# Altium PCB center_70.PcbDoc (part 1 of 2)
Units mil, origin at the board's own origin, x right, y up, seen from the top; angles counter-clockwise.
Board outline 2598.41 x 2598.41 mil, 6 copper layers (Top Layer 1, GND, POWER, SIG, GND (Mid4), Bottom Layer 1), stack 67.411 mil thick; 185 components, 89 nets, 515 pads, 179 vias.
Unrouted connection lines stored in the file: 158.
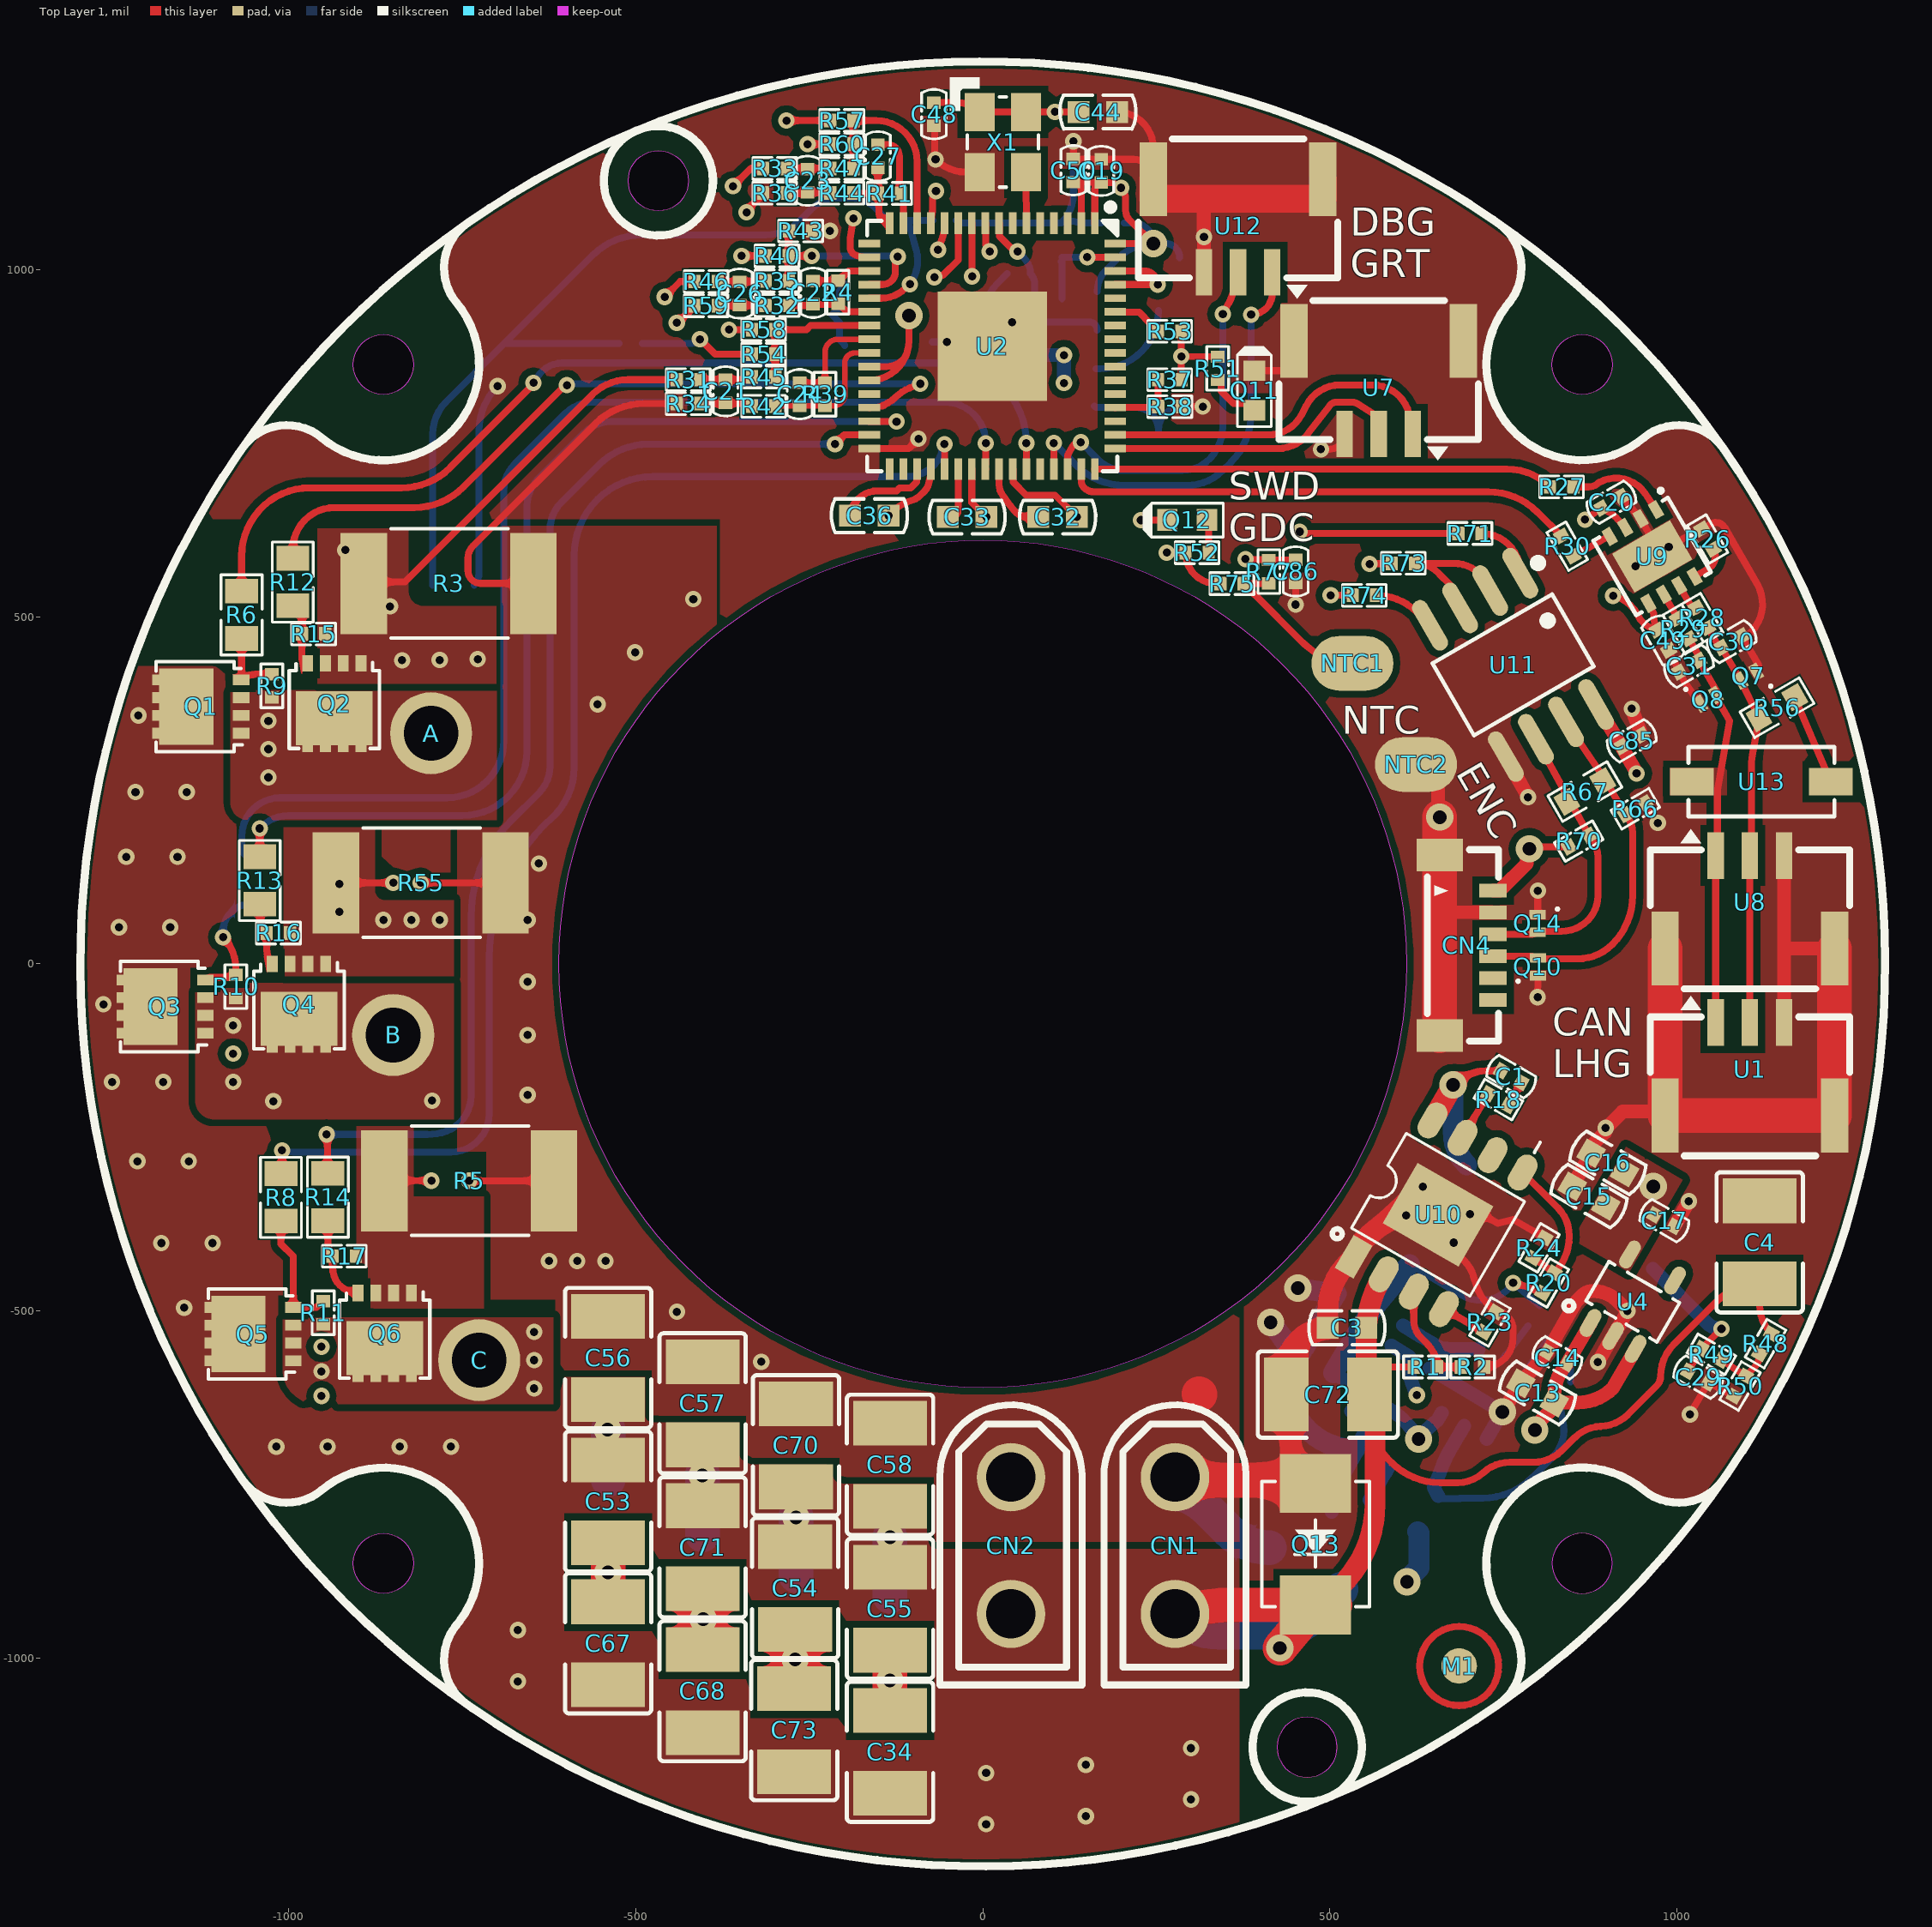
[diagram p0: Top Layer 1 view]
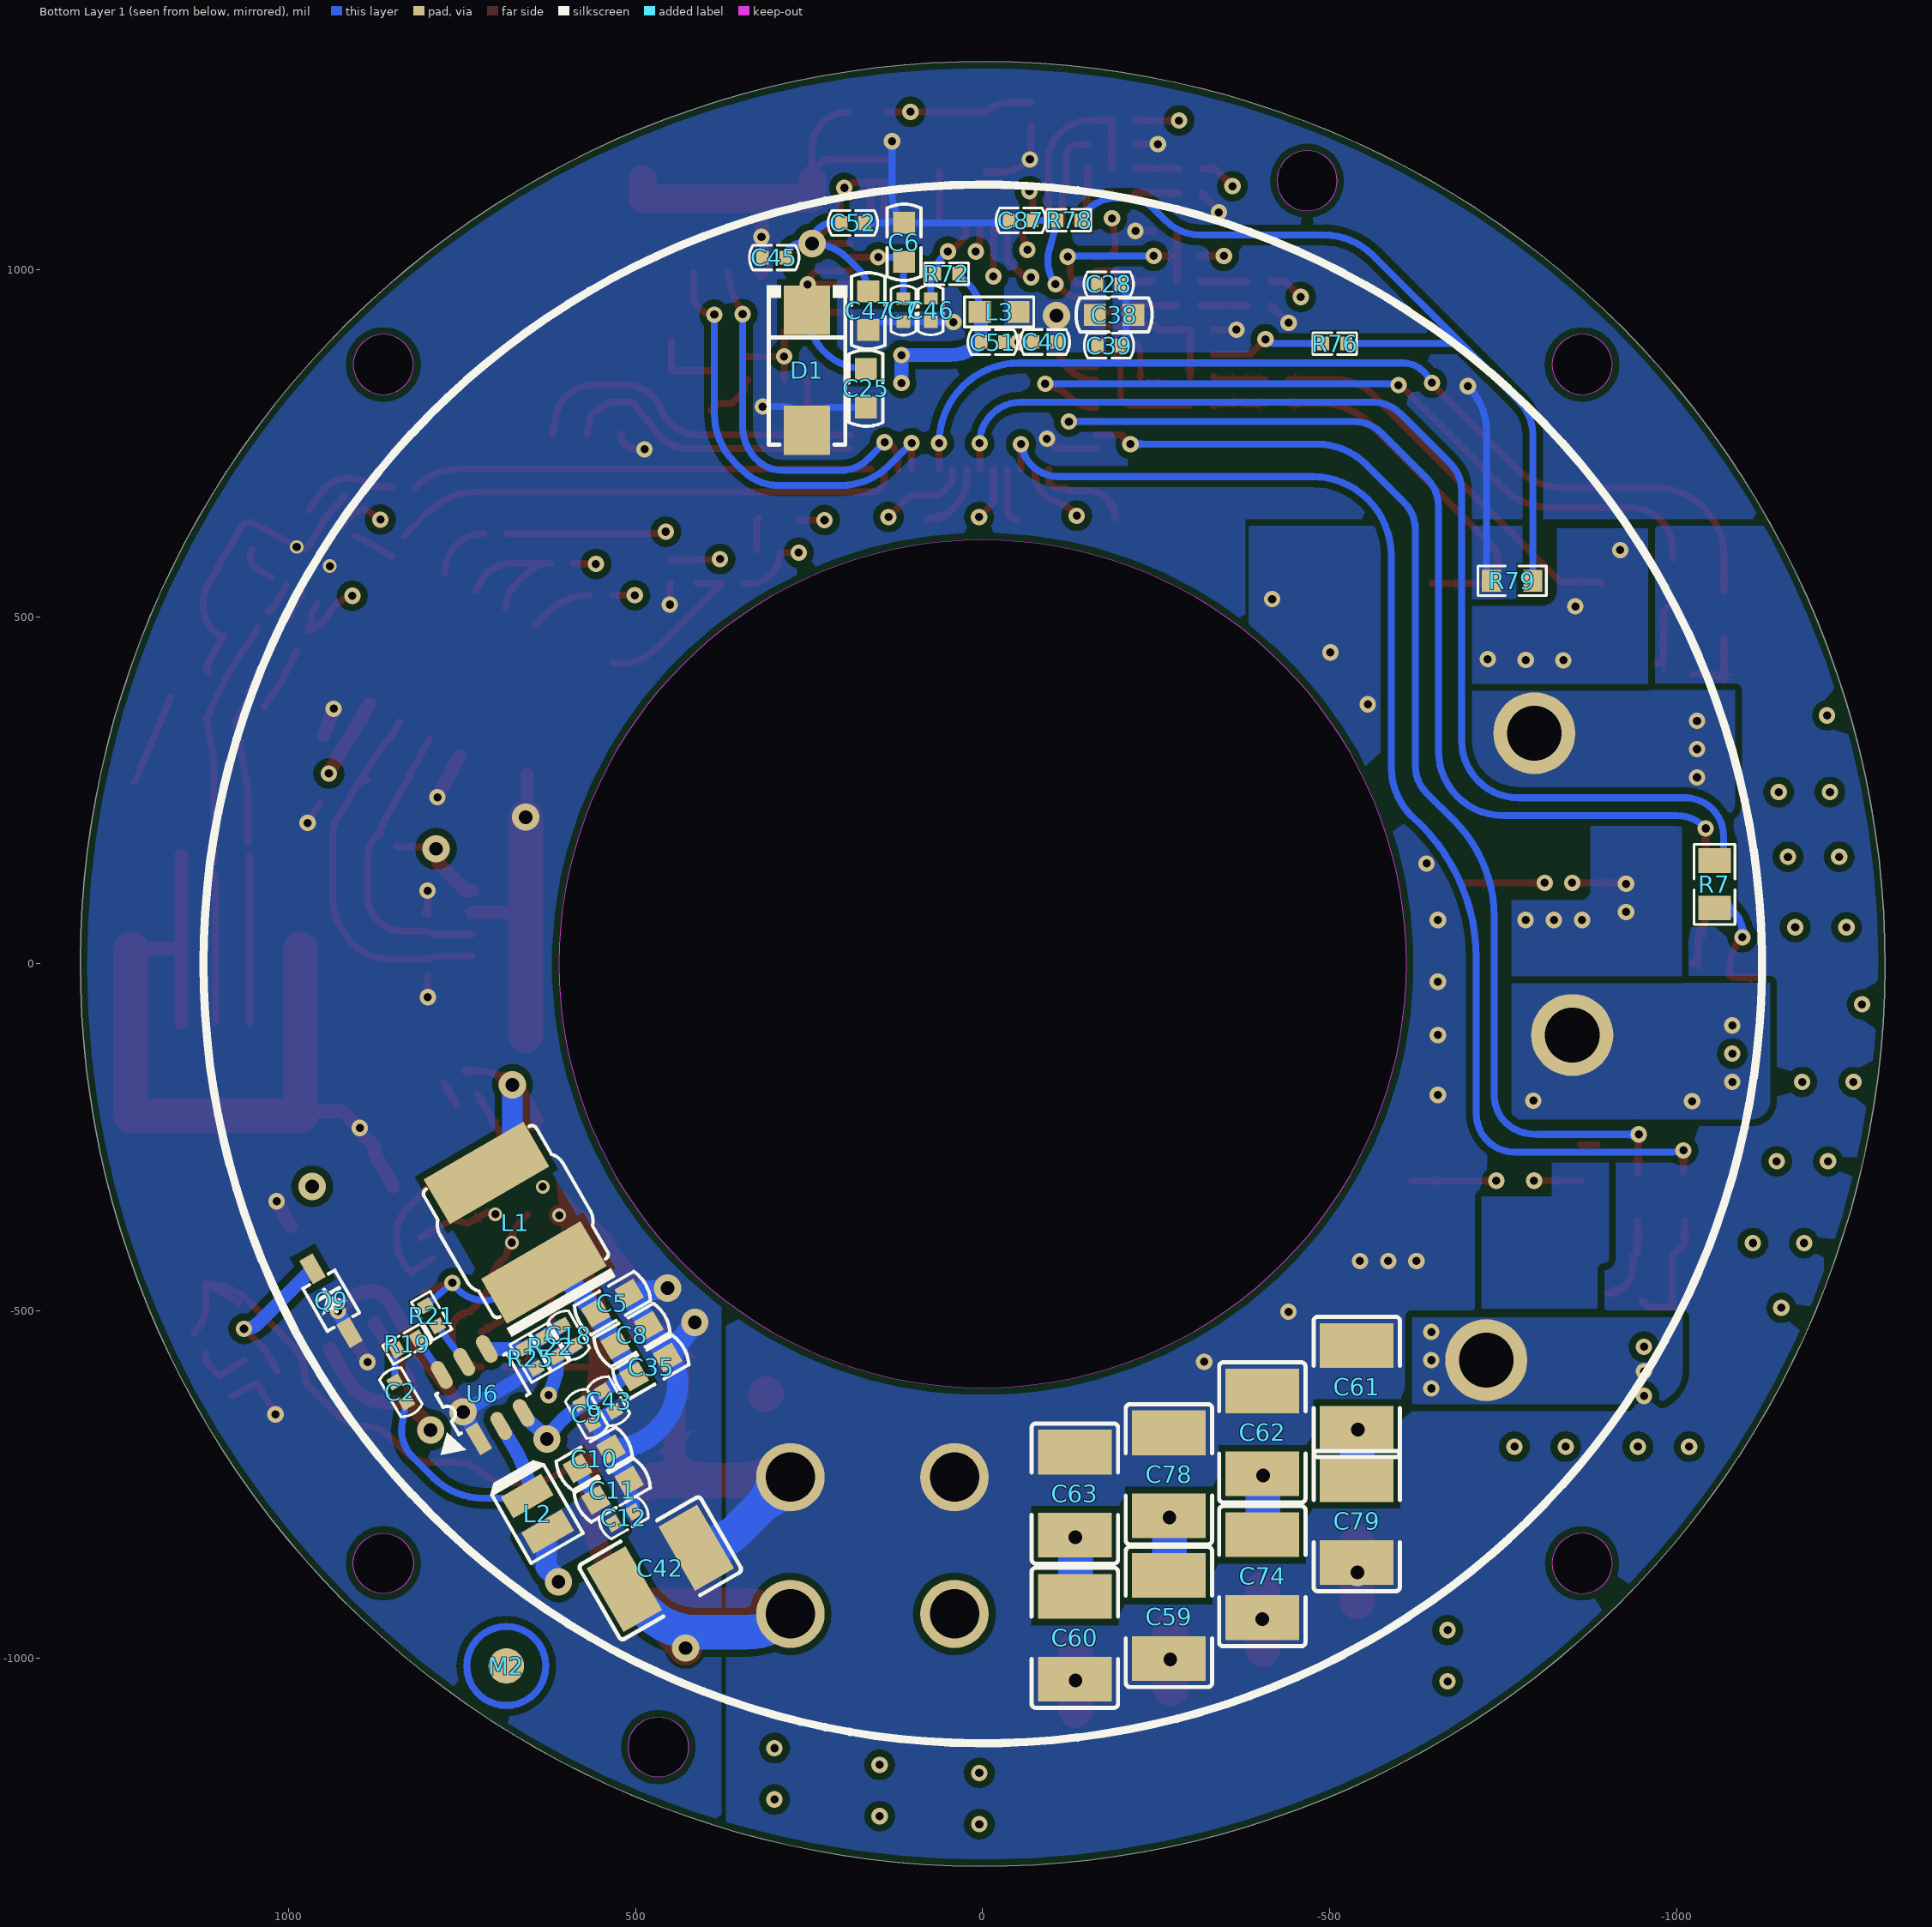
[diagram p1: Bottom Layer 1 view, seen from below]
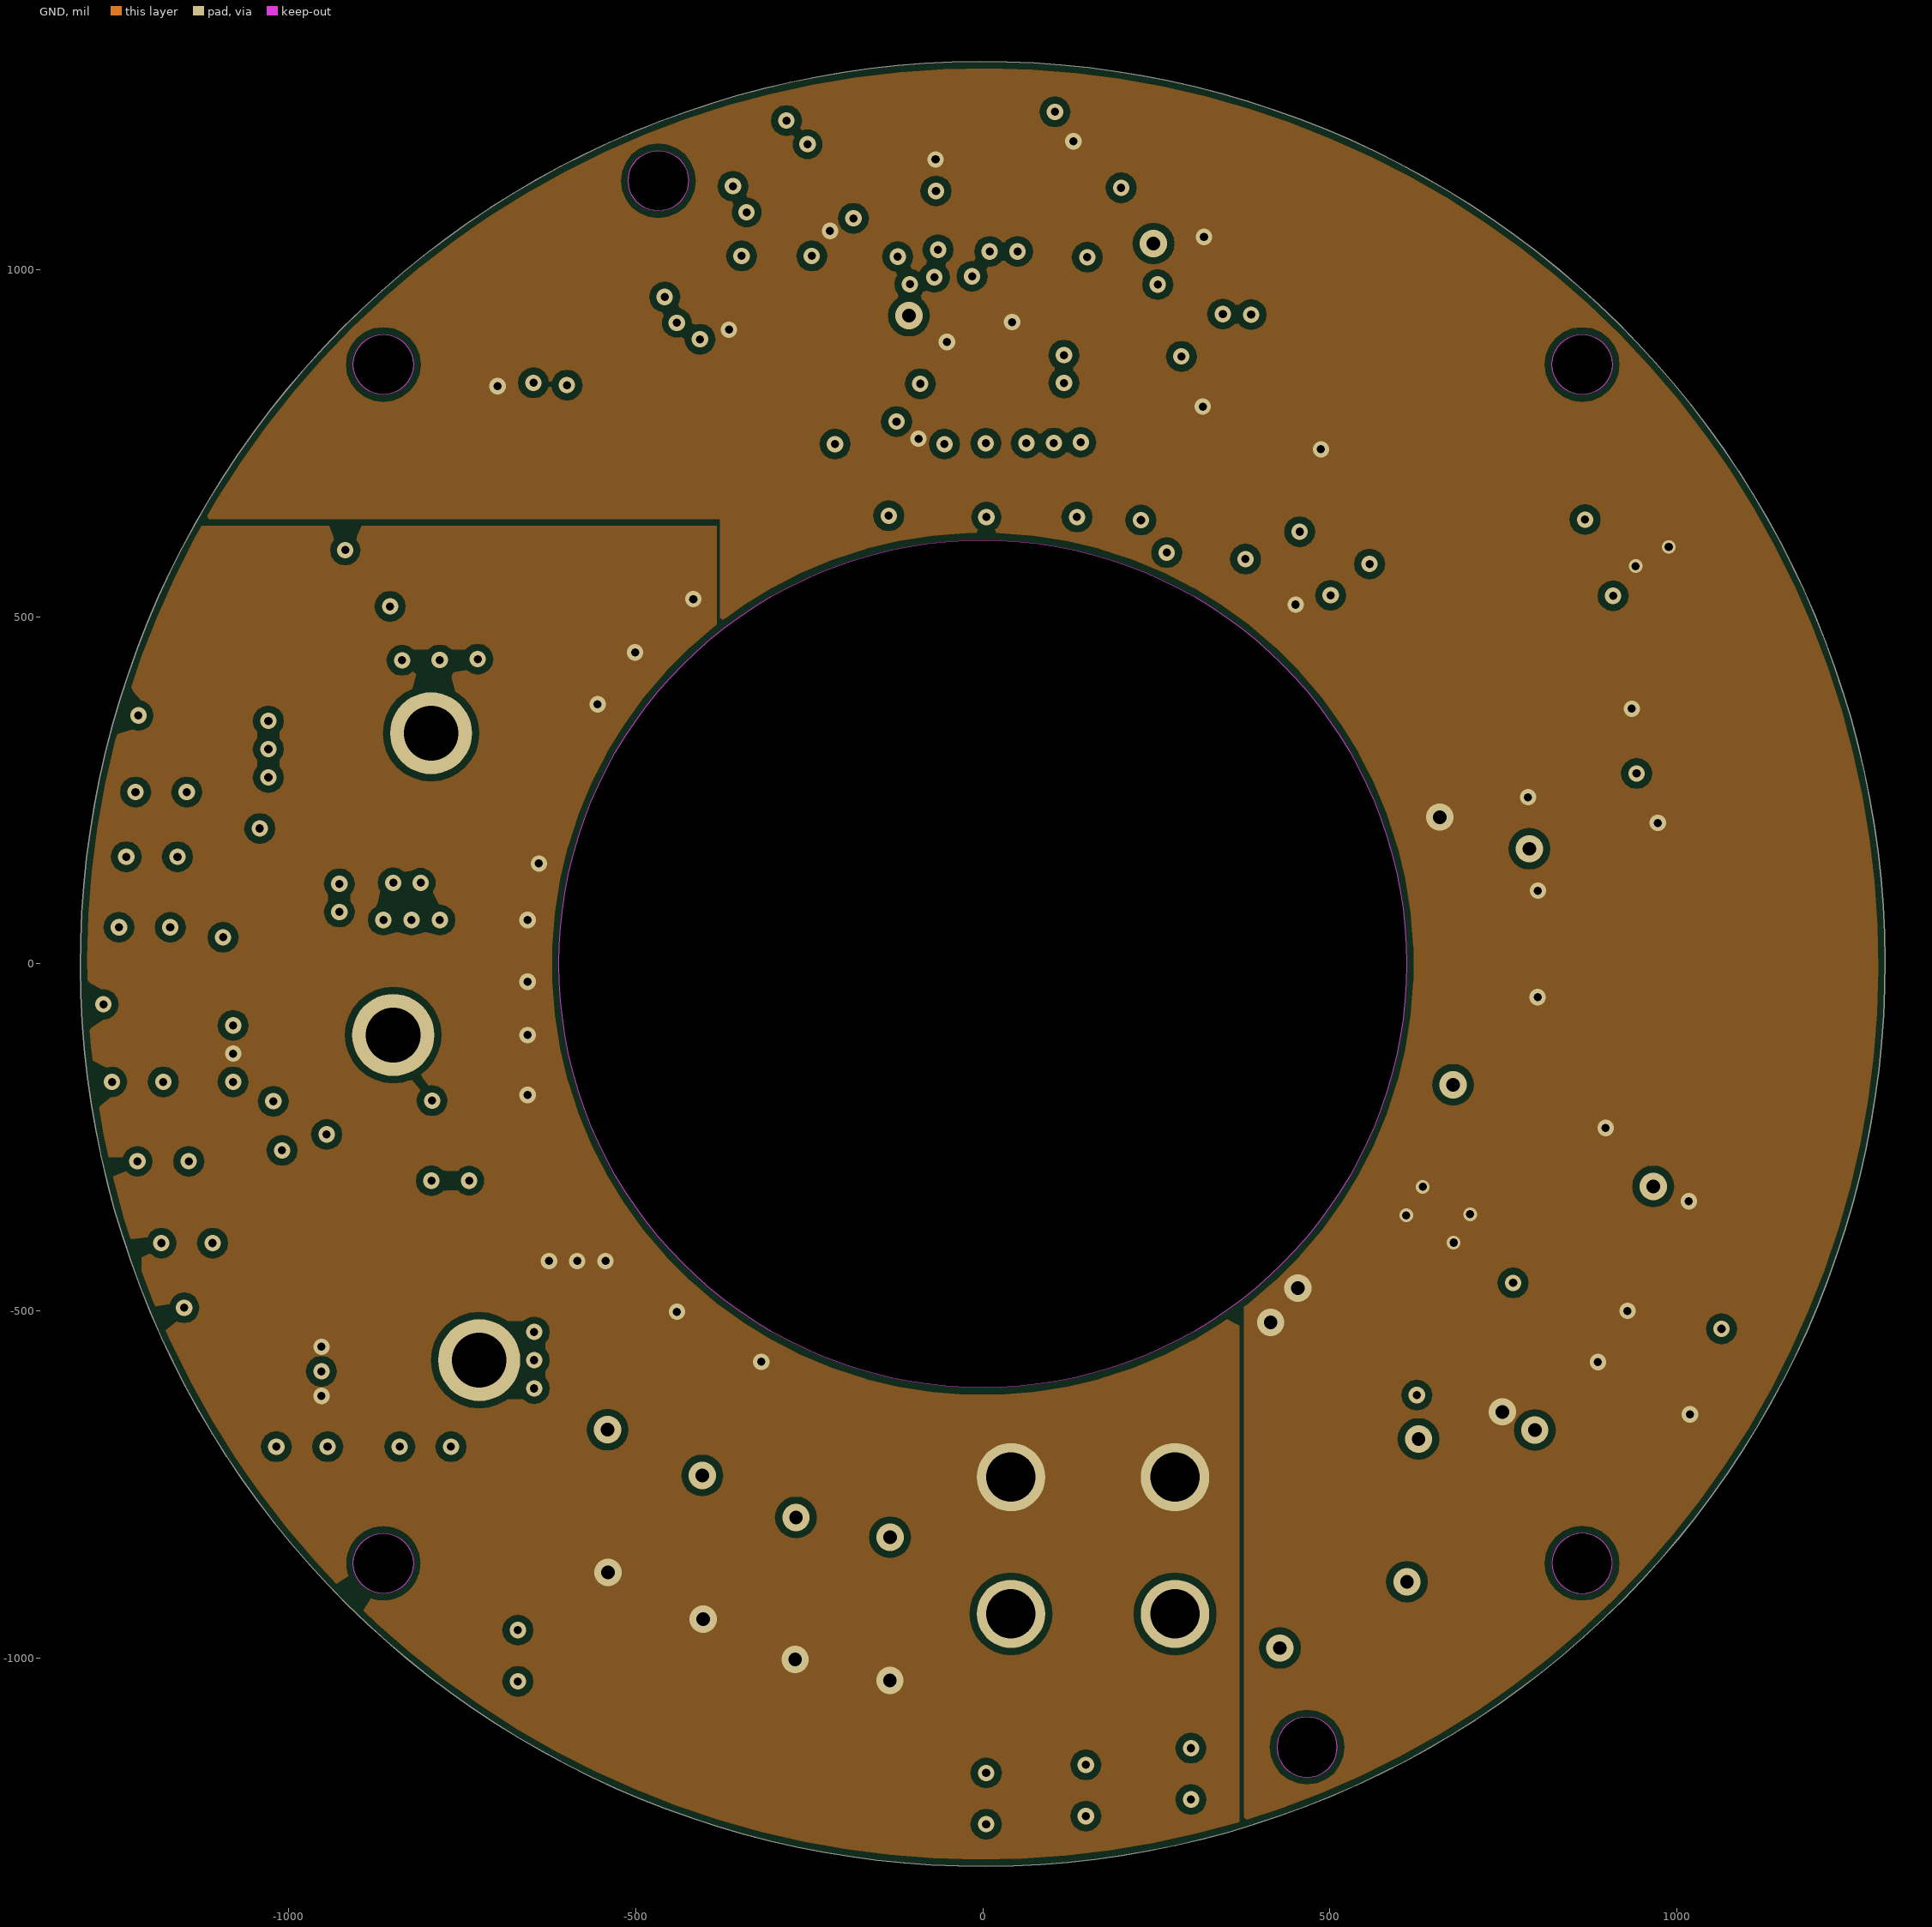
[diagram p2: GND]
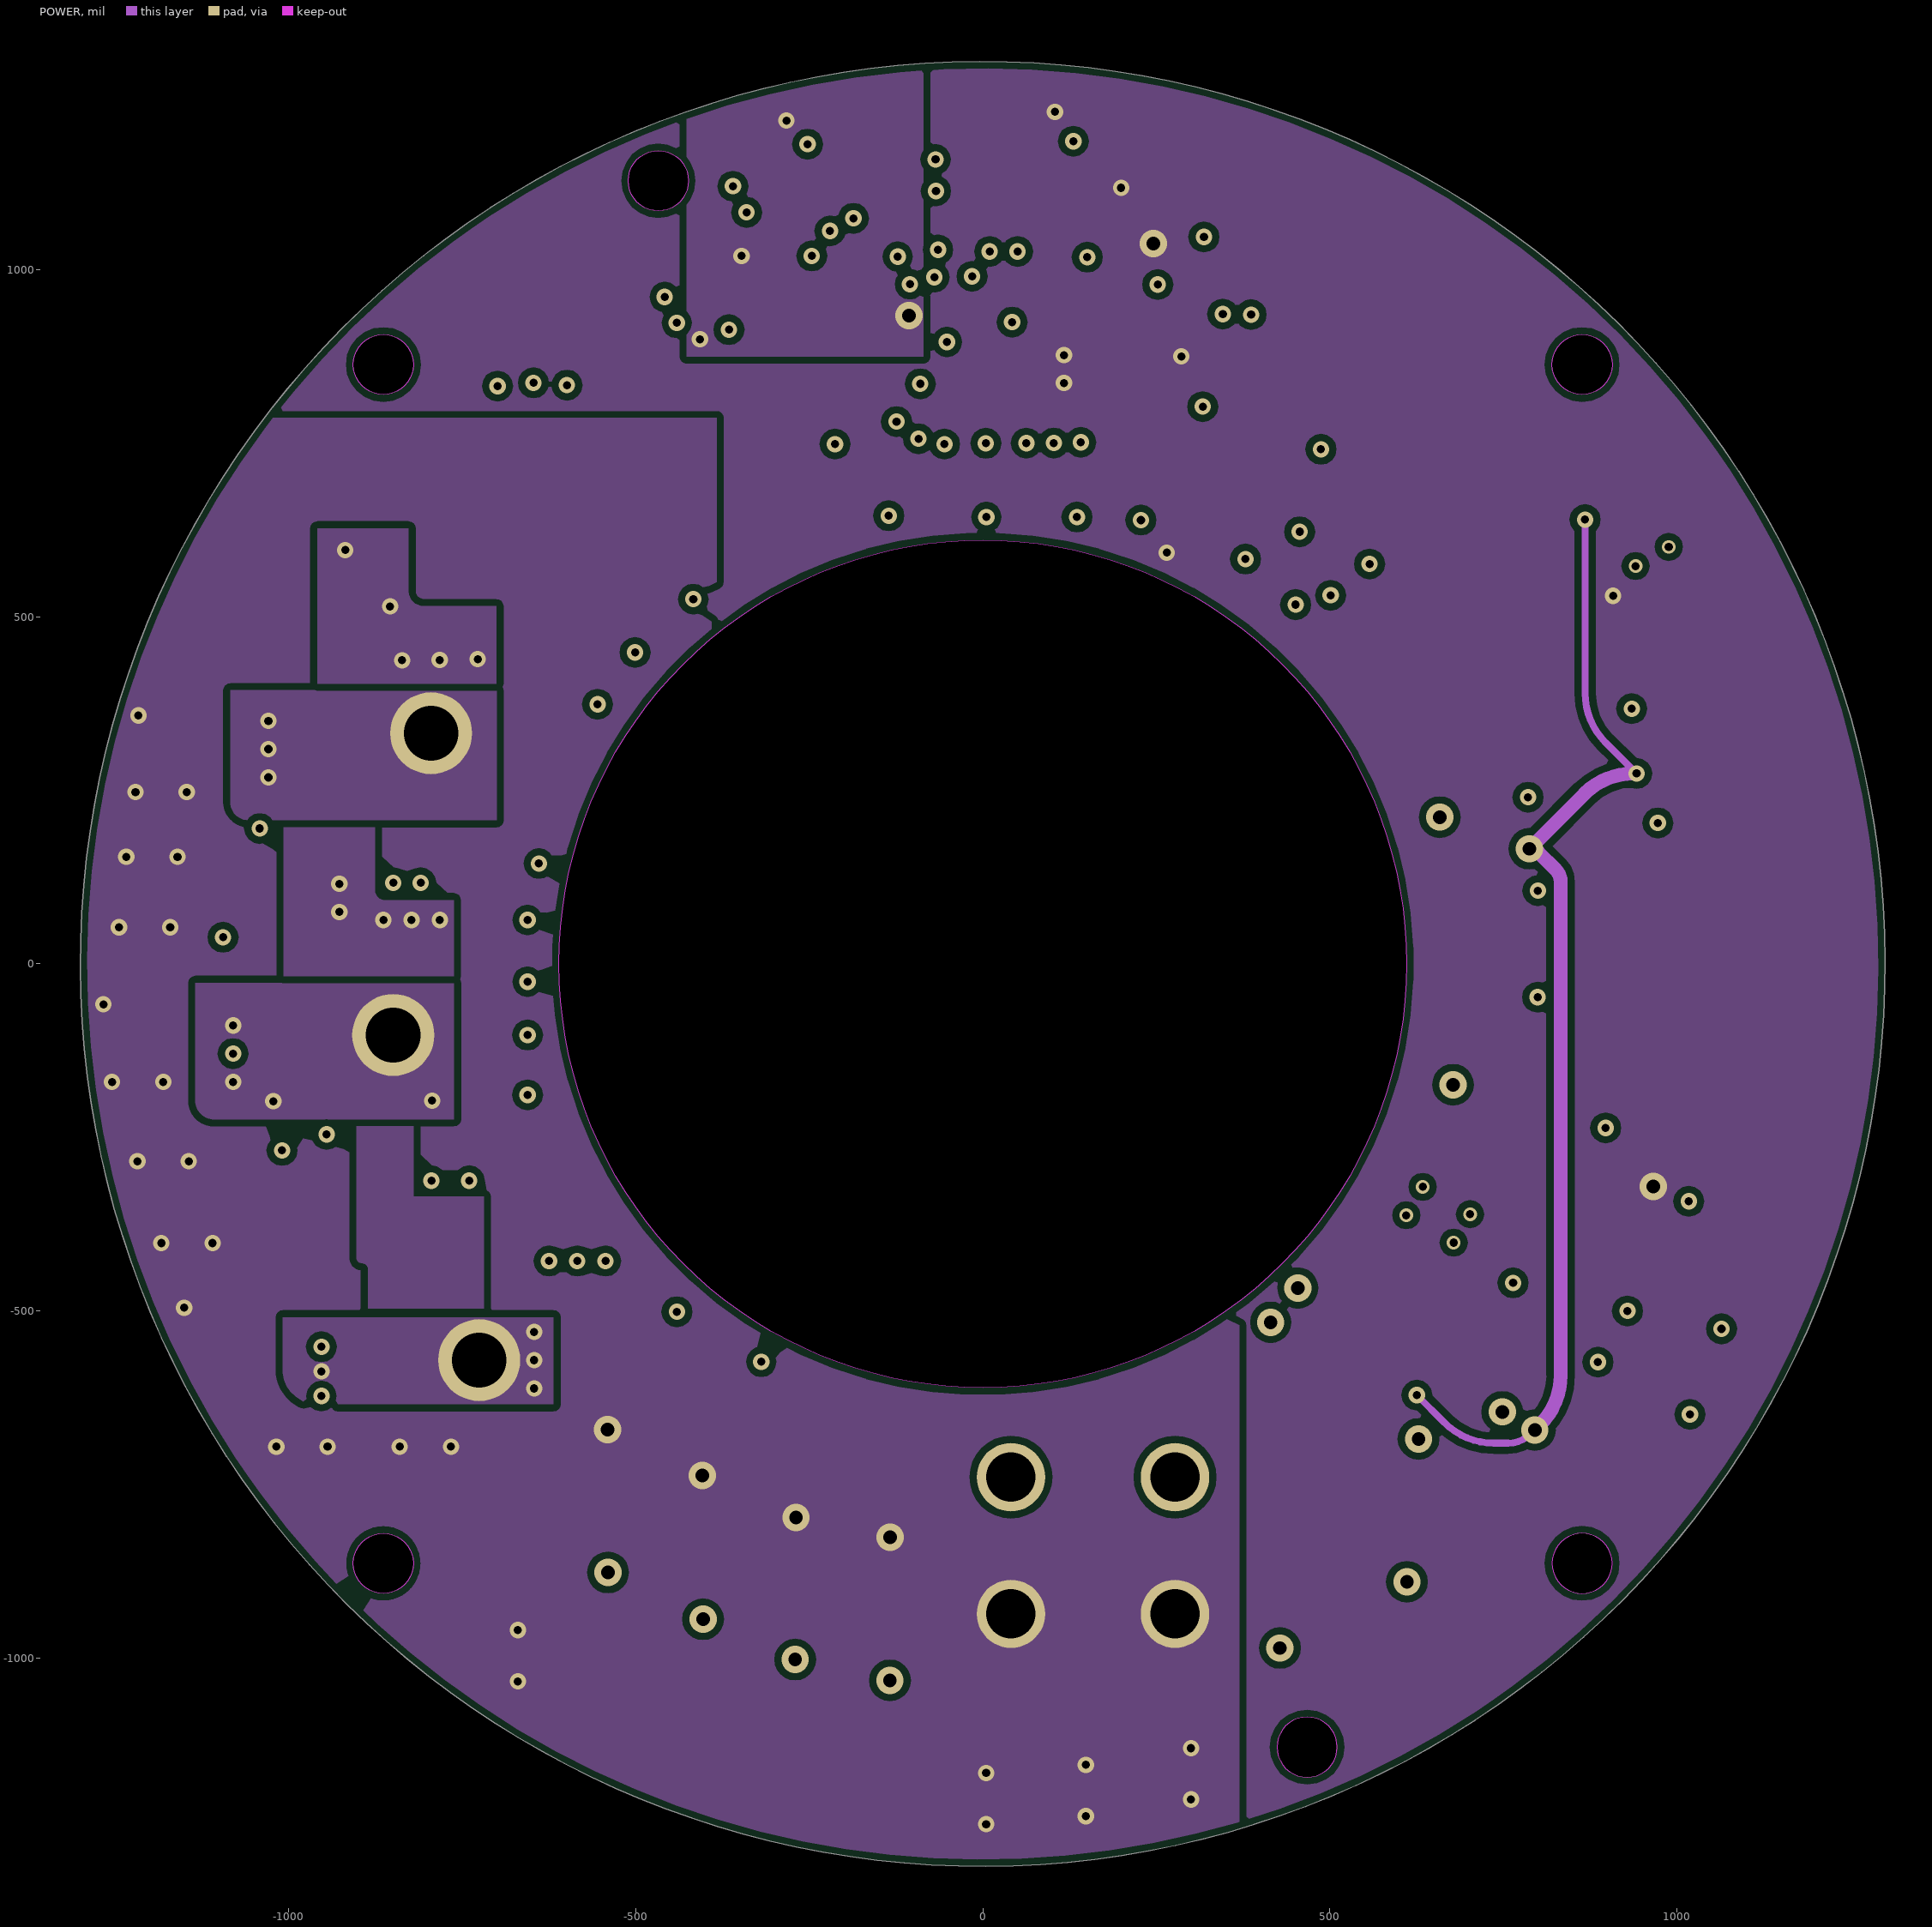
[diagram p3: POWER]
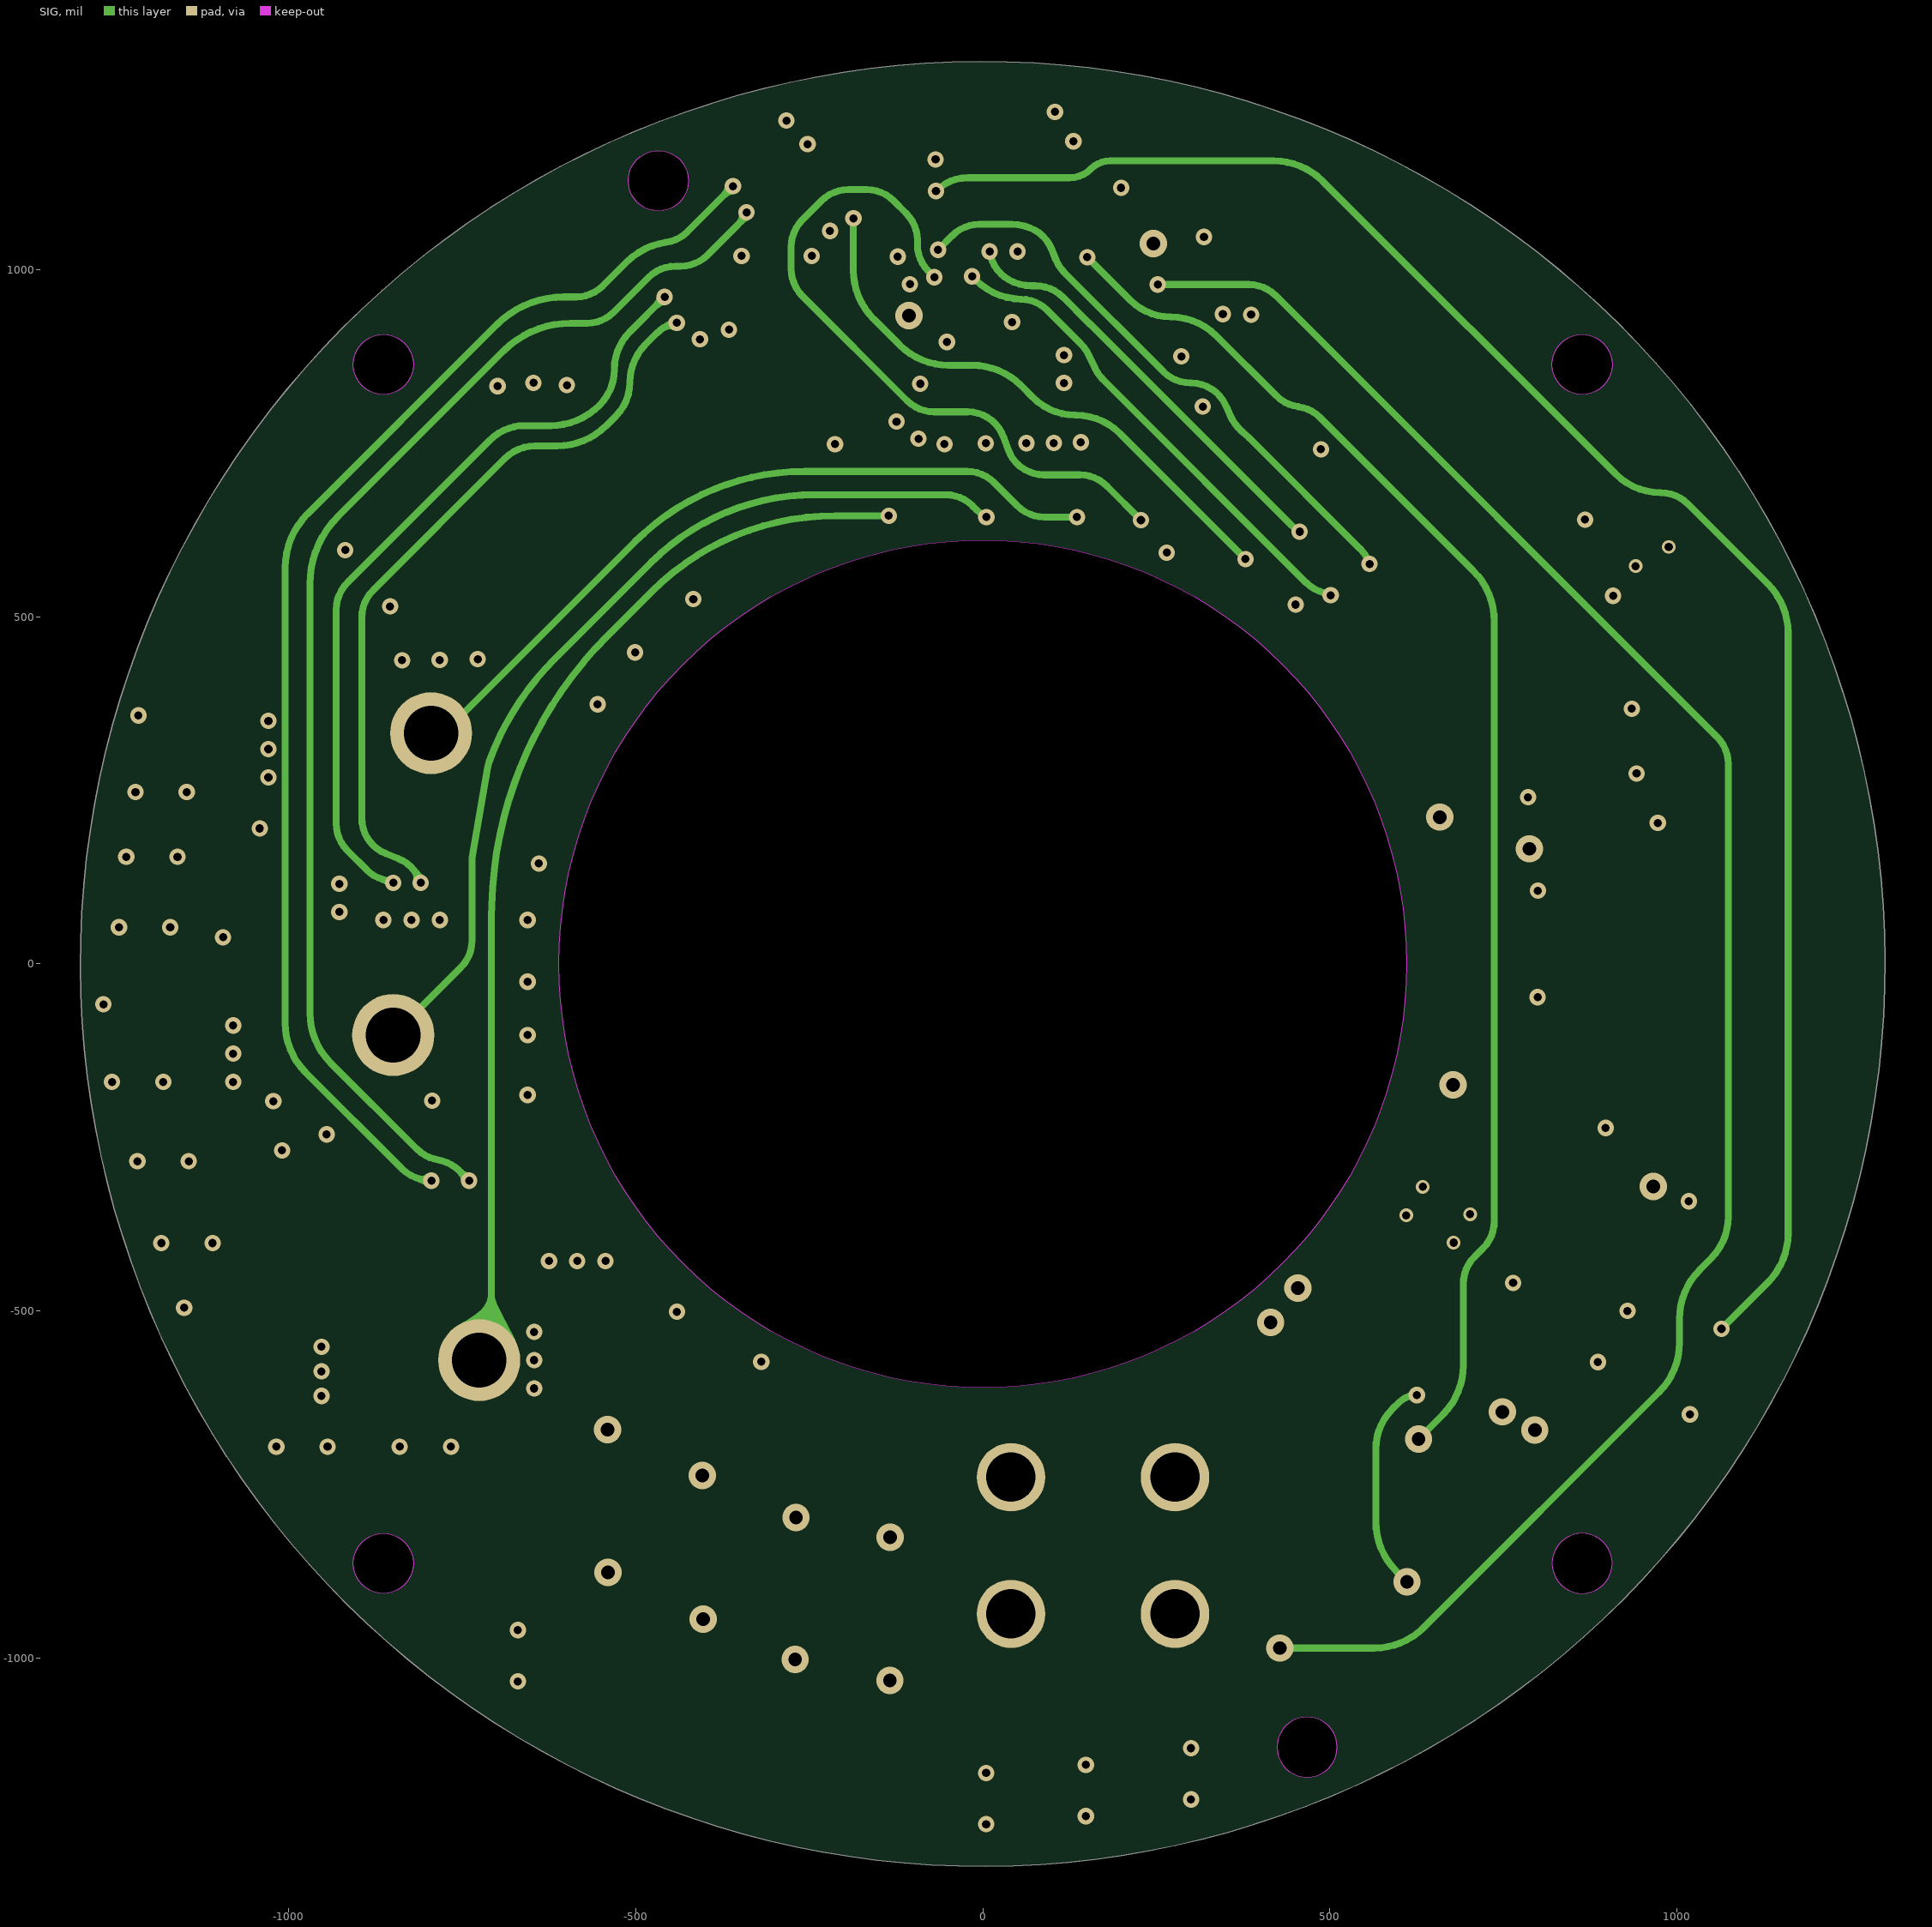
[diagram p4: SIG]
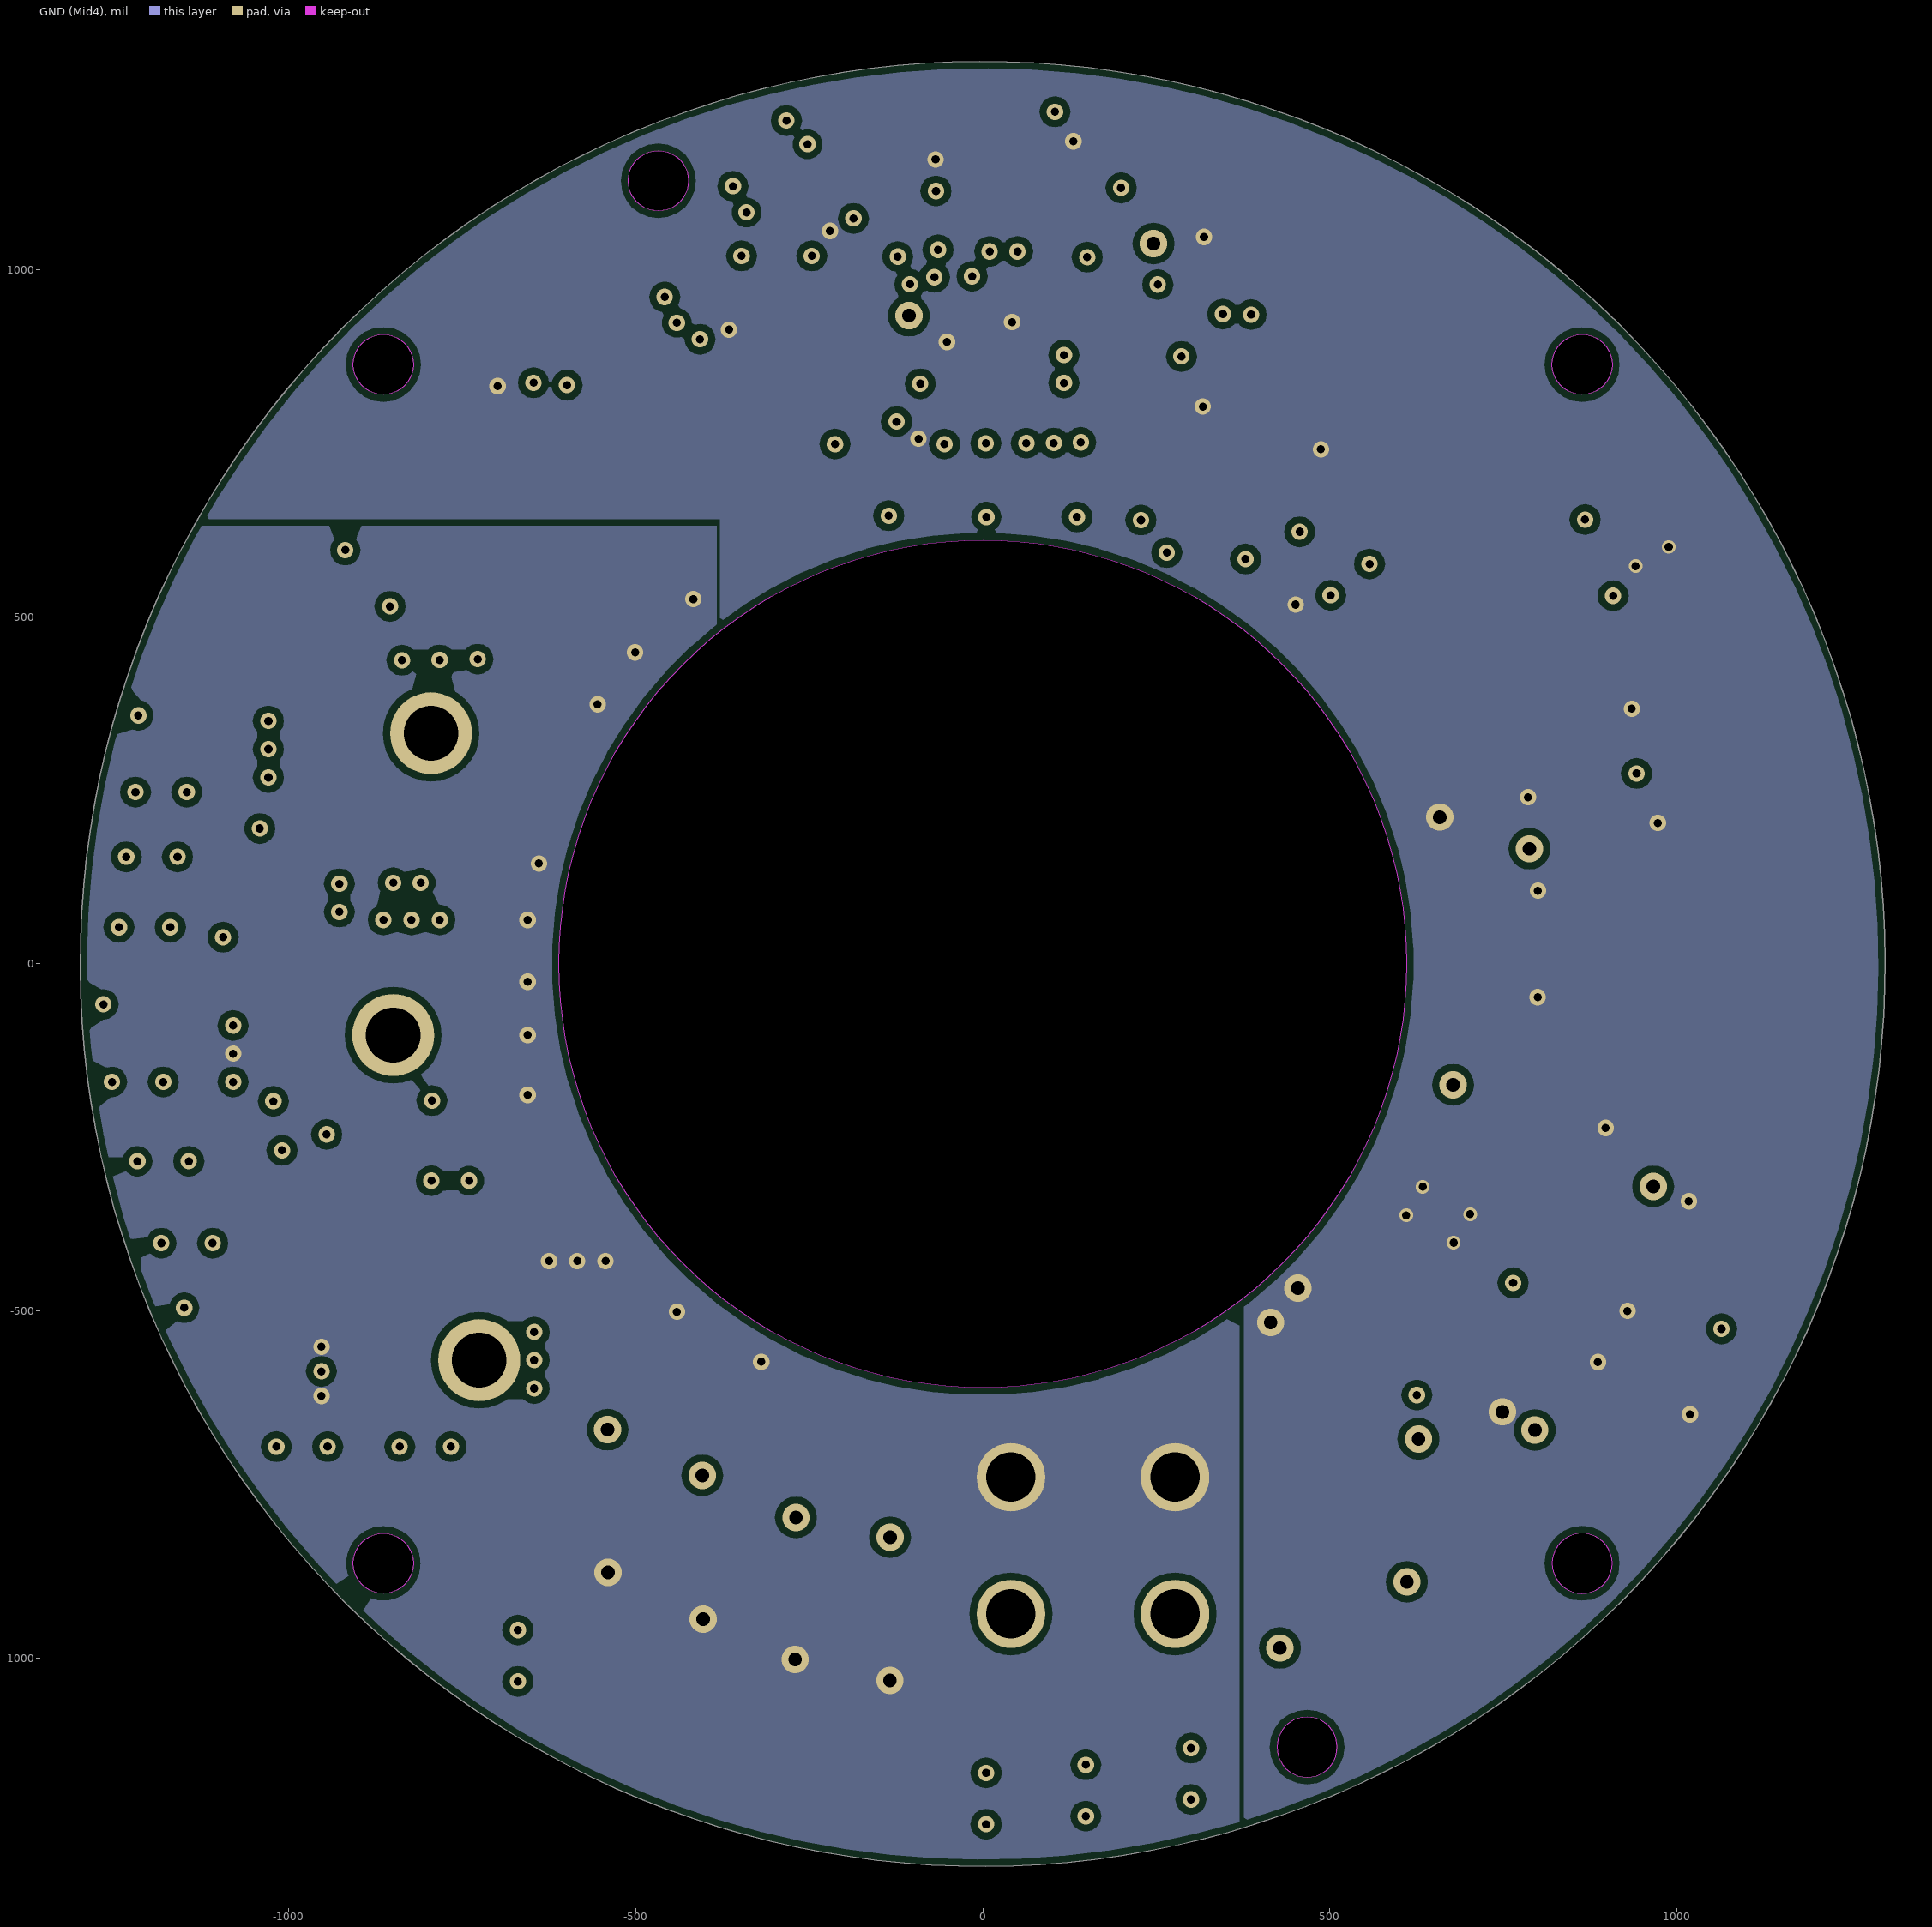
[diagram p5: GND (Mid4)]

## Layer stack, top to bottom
Top Solder: solder mask 1.9685, Solder Resist, Dk 3.5
Top Layer 1: signal copper 1.9685
Dielectric 2: prepreg 15.748, PP-006, Dk 4.1
GND: signal copper 1.378
Dielectric 4: prepreg 2.8, PP-006, Dk 4.1
POWER: signal copper 1.9685
Dielectric 1: dielectric 19.685, FR-4, Dk 4.8
SIG: signal copper 1.9685
Dielectric 5: prepreg 2.8, PP-006, Dk 4.1
GND (Mid4): signal copper 1.378
Dielectric 3: prepreg 15.748, PP-006, Dk 4.1
Bottom Layer 1: signal copper 1.9685
Bottom Solder: solder mask 1.9685, Solder Resist, Dk 3.5

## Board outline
-1066.59,-741.89 ccw(c-0.01,-0.01) 741.86,-1066.59 ccw(c-0.01,-0.01) 1066.56,741.86 ccw(c-0.01,-0.01) -741.89,1066.56 ccw(c-0.01,-0.01)
cut-out: 423.73,-1127.58 ccw(c467.04,-1127.58) 467.04,-1170.89 ccw(c467.04,-1127.58) 510.35,-1127.58 ccw(c467.04,-1127.58) 467.04,-1084.28 ccw(c467.04,-1127.58)
cut-out: 819.68,-863.02 ccw(c862.99,-863.02) 862.99,-906.33 ccw(c862.99,-863.02) 906.3,-863.02 ccw(c862.99,-863.02) 862.99,-819.71 ccw(c862.99,-863.02)
cut-out: 862.99,819.68 cw(c862.99,862.99) 819.68,862.99 cw(c862.99,862.99) 862.99,906.3 cw(c862.99,862.99) 906.3,862.99 cw(c862.99,862.99)
cut-out: -467.07,1084.25 cw(c-467.07,1127.56) -510.38,1127.56 cw(c-467.07,1127.56) -467.07,1170.86 cw(c-467.07,1127.56) -423.76,1127.56 cw(c-467.07,1127.56)
cut-out: -863.02,819.68 cw(c-863.02,862.99) -906.33,862.99 cw(c-863.02,862.99) -863.02,906.3 cw(c-863.02,862.99) -819.71,862.99 cw(c-863.02,862.99)
cut-out: -863.02,-906.33 cw(c-863.02,-863.02) -906.33,-863.02 cw(c-863.02,-863.02) -863.02,-819.71 cw(c-863.02,-863.02) -819.71,-863.02 cw(c-863.02,-863.02)
cut-out: 0,-610.24 cw(c0,0) -610.24,0 cw(c0,0) 0,610.24 cw(c0,0) 610.24,0 cw(c0,0)

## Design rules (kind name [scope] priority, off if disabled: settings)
BoardOutlineClearance [All] p1: gap=10 ignorepadtopadclearanceinfootprint=FALSE except(0: Arc-SplitContinuation Track-SplitContinuation SMDPad-SplitContinuation THPad-SplitContinuation Via-SplitContinuation Fill-SplitContinuation Poly-SplitContinuation Region-SplitContinuation Text-SplitContinuation)
Clearance [All] p1: gap=10 ignorepadtopadclearanceinfootprint=FALSE except(0: Arc-Hole Track-Hole SMDPad-Hole THPad-Hole Via-Hole Fill-Hole Poly-Hole Region-Hole Text-Hole; 7: Arc-Arc Arc-Track Arc-SMDPad Arc-THPad Arc-Via Track-Track Track-SMDPad Track-THPad Track-Via SMDPad-SMDPad SMDPad-THPad SMDPad-Via THPad-THPad THPad-Via Via-Via)
PlaneConnect [All] p1: planeconnectstyle=Direct reliefexpansion=20 reliefentries=4 reliefconductorwidth=10 reliefairgap=10
PolygonConnect PolygonConnect_25 [All vs IsNamedPolygon('GND-GND')] p1: connectstyle=Direct reliefconductorwidth=10 reliefentries=4 polygonreliefangle="90 Angle" airgapwidth=10
PolygonConnect PolygonConnect_24 [All vs IsNamedPolygon('GND-GND 1')] p2: connectstyle=Direct reliefconductorwidth=10 reliefentries=4 polygonreliefangle="90 Angle" airgapwidth=10
PolygonConnect PolygonConnect_23 [All vs IsNamedPolygon('POWER-3V3')] p3: connectstyle=Direct reliefconductorwidth=10 reliefentries=4 polygonreliefangle="90 Angle" airgapwidth=10
PolygonConnect PolygonConnect_22 [All vs IsNamedPolygon('Top Layer 1-GND')] p4: connectstyle=Direct reliefconductorwidth=10 reliefentries=4 polygonreliefangle="90 Angle" airgapwidth=10
PolygonConnect PolygonConnect_21 [All vs IsNamedPolygon('Top Layer 1-48V')] p5: connectstyle=Direct reliefconductorwidth=10 reliefentries=4 polygonreliefangle="90 Angle" airgapwidth=10
PolygonConnect PolygonConnect_20 [All vs IsNamedPolygon('Top Layer 1-C')] p6: connectstyle=Direct reliefconductorwidth=10 reliefentries=4 polygonreliefangle="90 Angle" airgapwidth=10
PolygonConnect PolygonConnect_19 [All vs IsNamedPolygon('Top Layer 1-NetQ6_S')] p7: connectstyle=Direct reliefconductorwidth=10 reliefentries=4 polygonreliefangle="90 Angle" airgapwidth=10
PolygonConnect PolygonConnect_18 [All vs IsNamedPolygon('Top Layer 1-B')] p8: connectstyle=Direct reliefconductorwidth=10 reliefentries=4 polygonreliefangle="90 Angle" airgapwidth=10
PolygonConnect PolygonConnect_17 [All vs IsNamedPolygon('Top Layer 1-NetQ4_S')] p9: connectstyle=Direct reliefconductorwidth=10 reliefentries=4 polygonreliefangle="90 Angle" airgapwidth=10
PolygonConnect PolygonConnect_16 [All vs IsNamedPolygon('Top Layer 1-A')] p10: connectstyle=Direct reliefconductorwidth=10 reliefentries=4 polygonreliefangle="90 Angle" airgapwidth=10
PolygonConnect PolygonConnect_15 [All vs IsNamedPolygon('Top Layer 1-NetQ2_S')] p11: connectstyle=Direct reliefconductorwidth=10 reliefentries=4 polygonreliefangle="90 Angle" airgapwidth=10
PolygonConnect PolygonConnect_14 [All vs IsNamedPolygon('POWER-3V3')] p12: connectstyle=Direct reliefconductorwidth=10 reliefentries=4 polygonreliefangle="90 Angle" airgapwidth=10
PolygonConnect PolygonConnect_13 [All vs IsNamedPolygon('POWER-A3V3')] p13: connectstyle=Direct reliefconductorwidth=10 reliefentries=4 polygonreliefangle="90 Angle" airgapwidth=10
PolygonConnect PolygonConnect_12 [All vs IsNamedPolygon('Top Layer 1-5V')] p14: connectstyle=Direct reliefconductorwidth=10 reliefentries=4 polygonreliefangle="90 Angle" airgapwidth=10
PolygonConnect PolygonConnect_11 [All vs IsNamedPolygon('Top Layer 1-GND 2')] p15: connectstyle=Direct reliefconductorwidth=10 reliefentries=4 polygonreliefangle="90 Angle" airgapwidth=10
PolygonConnect PolygonConnect_10 [All vs IsNamedPolygon('POWER-24V')] p16: connectstyle=Direct reliefconductorwidth=10 reliefentries=4 polygonreliefangle="90 Angle" airgapwidth=10
PolygonConnect PolygonConnect_9 [All vs IsNamedPolygon('Top Layer 1-NetC82_2')] p17: connectstyle=Direct reliefconductorwidth=10 reliefentries=4 polygonreliefangle="90 Angle" airgapwidth=10
PolygonConnect PolygonConnect_8 [All vs IsNamedPolygon('Top Layer 1-NetQ2_S')] p18: connectstyle=Direct reliefconductorwidth=10 reliefentries=4 polygonreliefangle="90 Angle" airgapwidth=10
PolygonConnect PolygonConnect_7 [All vs IsNamedPolygon('Top Layer 1-A')] p19: connectstyle=Direct reliefconductorwidth=10 reliefentries=4 polygonreliefangle="90 Angle" airgapwidth=10
PolygonConnect PolygonConnect_6 [All vs IsNamedPolygon('Top Layer 1-B')] p20: connectstyle=Direct reliefconductorwidth=10 reliefentries=4 polygonreliefangle="90 Angle" airgapwidth=10
PolygonConnect PolygonConnect_5 [All vs IsNamedPolygon('Top Layer 1-C')] p21: connectstyle=Direct reliefconductorwidth=10 reliefentries=4 polygonreliefangle="90 Angle" airgapwidth=10
PolygonConnect PolygonConnect_4 [All vs IsNamedPolygon('Top Layer 1-GND 1')] p22: connectstyle=Direct reliefconductorwidth=10 reliefentries=4 polygonreliefangle="90 Angle" airgapwidth=10
PolygonConnect PolygonConnect_3 [All vs IsNamedPolygon('Top Layer 1-48V')] p23: connectstyle=Direct reliefconductorwidth=10 reliefentries=4 polygonreliefangle="90 Angle" airgapwidth=10
PolygonConnect PolygonConnect_2 [All vs IsNamedPolygon('Top Layer 1-GND')] p24: connectstyle=Direct reliefconductorwidth=10 reliefentries=4 polygonreliefangle="90 Angle" airgapwidth=10
PolygonConnect PolygonConnect_1 [All vs IsNamedPolygon('Top Layer 1-A')] p25: connectstyle=Direct reliefconductorwidth=10 reliefentries=4 polygonreliefangle="90 Angle" airgapwidth=10
PolygonConnect [All] p26: connectstyle=Relief reliefconductorwidth=10 reliefentries=4 polygonreliefangle="90 Angle" airgapwidth=10
RoutingVias [All] p1: holewidth=11.81 width=23.62 viastyle="Through Hole" minholewidth=3.94 minwidth=7.87 maxholewidth=98.43 maxwidth=196.85
SolderMaskExpansion [All] p1: expansion=4 istentingtop=FALSE
Width [All] p1: maxlimit=200 minlimit=1 preferedwidth=10 midlayer3_minwidth=10 midlayer3_maxwidth=10 midlayer4_minwidth=10 midlayer4_maxwidth=10 minimp=50.000000 maximp=50.000000 favimp=50.000000
29 further rules are at their usual default settings.

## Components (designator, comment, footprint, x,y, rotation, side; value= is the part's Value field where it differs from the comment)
A "PowerPad" D25_Power -794.29,332.09 r270 top
B "PowerPad" D25_Power -848.82,-102.36 r270 top
C "PowerPad" D25_Power -725,-570.47 r270 top
C1 "0.1uF(50V)" C0402 761.05,-162.23 r330 top
C2 "0.1uF(50V)" C0402 837.8,-616.54 r60 bottom
C3 "0.1uF(100V)" C0603 524.46,-523.96 r0 top
C4 "" C1210 1118.7,-400.79 r270 top
C5 "10uF(25V)" C0603 533.09,-488.45 r330 bottom
C6 "10uF(25V)" C0603 113.19,1038.99 r270 bottom
C7 "0.1uF(50V)" C0402 114.19,941.04 r90 bottom
C8 "10uF(25V)" C0603 504.9,-534.48 r330 bottom
C9 "0.1uF(50V)" C0402 570.28,-647.83 r60 bottom
C10 "10uF(25V)" C0603 559.33,-712.58 r330 bottom
C11 "10uF(25V)" C0603 533.17,-757.9 r330 bottom
C12 "0.1uF(50V)" C0402 516.96,-797.24 r330 bottom
C13 "10uF(25V)" C0603 798.88,-617.62 r330 top
C14 "0.1uF(50V)" C0402 827.36,-567.08 r330 top
C15 "10uF(25V)" C0603 872.86,-334.22 r330 top
C16 "10uF(25V)" C0603 900.03,-286.32 r330 top
C17 "0.1uF(50V)" C0402 981.45,-369.64 r150 top
C18 "100pF(50V)" C0402 596.65,-534.84 r240 bottom
C19 "0.1uF(50V)" C0402 170.67,1141.73 r270 top
C20 "0.1uF(50V)" C0402 905.16,664.66 r210 top
C21 "220pF(50V)" C0402 -370.28,824.39 r90 top
C22 "220pF(50V)" C0402 -244.29,966.33 r270 top
C23 "220pF(50V)" C0402 -252.17,1127.56 r90 top
C24 "220pF(50V)" C0402 -263.58,820.26 r270 top
C25 "0.1uF(100V)" C0603 168.11,828.94 r90 bottom
C26 "220pF(50V)" C0402 -349.8,965.16 r90 top
C27 "220pF(50V)" C0402 -150.99,1162.79 r270 top
C28 "0.1uF(50V)" C0402 -181.5,978.54 r0 bottom
C29 "100pF(50V)" C0402 1030.32,-594.88 r150 top
C30 "10pF(50V)" C0402 1078.32,464.02 r30 top
C31 "10pF(50V)" C0402 1016.95,428.58 r30 top
C32 "10uF(25V)" C0603 107.87,643.33 r180 top
C33 "10uF(25V)" C0603 -22.52,643.33 r180 top
C34 "" C1210 -133.46,-1134.45 r270 top
C35 "10uF(25V)" C0603 477.81,-580.42 r330 bottom
C36 "10uF(25V)" C0603 -163.19,645.28 r180 top
C38 "10uF(25V)" C0603 -189.17,934.45 r0 bottom
C39 "0.1uF(50V)" C0402 -181.89,890.16 r0 bottom
C40 "0.1uF(50V)" C0402 -89.57,895.47 r180 bottom
C42 "" C1210 464.24,-870.26 r330 bottom
C43 "0.1uF(50V)" C0402 538.78,-629.53 r60 bottom
C44 "10uF(25V)" C0603 165.83,1226.57 r180 top
C45 "0.1uF(50V)" C0402 300.2,1016.93 r180 bottom
C46 "0.1uF(50V)" C0402 74.8,941.34 r90 bottom
C47 "10uF(25V)" C0603 164.82,940.26 r90 bottom
C48 "0.1uF(50V)" C0402 -70.28,1223.43 r90 top
C49 "0.1uF(50V)" C0402 979.42,466.02 r120 top
C50 "0.1uF(50V)" C0402 130.51,1142.52 r270 top
C51 "0.1uF(50V)" C0402 -14.37,895.08 r0 bottom
C52 "0.1uF(50V)" C0402 186.86,1066.8 r0 bottom
C53 "" C1210 -539.38,-773.82 r90 top
C54 "" C1210 -270.08,-898.62 r90 top
C55 "" C1210 -133.46,-928.35 r90 top
C56 "" C1210 -539.38,-567.32 r270 top
C57 "" C1210 -403.35,-632.68 r270 top
C58 "" C1210 -133.46,-721.06 r270 top
C59 "" C1210 -268.11,-940.24 r90 bottom
C60 "" C1210 -132.68,-970.21 r90 bottom
C61 "" C1210 -538.59,-609.06 r270 bottom
C62 "" C1210 -402.56,-674.52 r270 bottom
C63 "" C1210 -132.68,-762.6 r270 bottom
C67 "" C1210 -539.38,-978.15 r270 top
C68 "" C1210 -403.35,-1047.05 r270 top
C70 "" C1210 -268.9,-693.11 r270 top
C71 "" C1210 -403.35,-839.76 r90 top
C72 "" C1210 496.9,-619.87 r0 top
C73 "" C1210 -271.46,-1103.15 r270 top
C74 "" C1210 -402.56,-881.48 r90 bottom
C78 "" C1210 -268.11,-734.85 r270 bottom
C79 "" C1210 -538.59,-802.17 r90 bottom
C85 "0.1uF(50V)" C0402 934.45,321.26 r210 top
C86 "0.1uF(50V)" C0402 450.59,565.16 r90 top
C87 "0.1uF(50V)" C0402 -54.92,1070.47 r180 bottom
CN1 "XT30UPB-M" CONN-TH_XT30UPB-M 276.87,-837.33 r270 top
CN2 "XT30UPB-M" CONN-TH_XT30UPB-M 40.65,-837.33 r270 top
CN4 "SM06B-SURS-TF(LF)(SN)" CONN-SMD_SM06B-SURS-TF-LF-SN 696.46,26.77 r270 top
D1 "1SMA4761AG" SMA_L4.4-W2.6-LS5.0-RD 252.95,854.72 r270 bottom
L1 "SWPA5020S150MT" L(5*2.0)-S 673.23,-372.64 r240 bottom value=15uH
L2 "CKCSA201610-4.7uH/M" L(2*1.6*1)-S 641.11,-791.85 r240 bottom value=15uH
L3 "HCB1608KF-121T20" L0603 -23.72,938.77 r180 bottom value=15uH
M1 "marker" MARK 686.02,-1010.83 r0 top
M2 "marker" MARK 686.02,-1010.83 r180 bottom
NTC1 "TP" ICT2 532.28,432.87 r90 top
NTC2 "TP" ICT2 623.82,287.2 r270 top
Q1 "NCEP11N10AQU" DFN3.3X3.3-8L -1146.8,370.47 r180 top
Q2 "NCEP11N10AQU" DFN3.3X3.3-8L -933.61,353.54 r270 top
Q3 "NCEP11N10AQU" DFN3.3X3.3-8L -1198.41,-61.42 r180 top
Q4 "NCEP11N10AQU" DFN3.3X3.3-8L -984.45,-79.13 r270 top
Q5 "NCEP11N10AQU" DFN3.3X3.3-8L -1071.84,-532.87 r180 top
Q6 "NCEP11N10AQU" DFN3.3X3.3-8L -861.03,-552.96 r270 top
Q7 "ESDLC12VLB" DFN65P100X45-2N 1102.47,414.31 r210 top
Q8 "ESDLC12VLB" DFN65P100X45-2N 1044.51,380.85 r30 top
Q9 "BZT52C3V3" DIODE-S-12 938.19,-484.84 r240 bottom
Q10 "ESDLC12VLB" DFN65P100X45-2N 799.41,-4.13 r90 top
Q11 "YLS191/G/21/06" LED-S0603 391.14,825.59 r90 top
Q12 "YLS191/G/21/06" LED-S0603 294.29,638.98 r180 top
Q13 "SMBJ58A" DIODE-SMB-3 479.22,-835.36 r90 top
Q14 "ESDLC12VLB" DFN65P100X45-2N 799.02,58.27 r270 top
R1 "280KR" R0402 637.44,-580.31 r0 top
R2 "20KR" R0402 705.2,-580.31 r180 top
R3 "50mR" R2512-4 -769.09,547.83 r180 top
R4 "10KR" R0402 -208.28,967.2 r90 top
R5 "50mR" R2512-4 -739.38,-312.17 r180 top
R6 "33R" R0805 -1067.08,502.54 r270 top
R7 "33R" R0805 -1053.73,114.6 r270 bottom
R8 "33R" R0805 -1010.43,-336.02 r270 top
R9 "10KR" R0402 -1023.57,400.4 r270 top
R10 "10KR" R0402 -1075.39,-32.68 r270 top
R11 "10KR" R0402 -949.65,-502.36 r270 top
R12 "33R" R0805 -993.45,549.83 r270 top
R13 "33R" R0805 -1040.93,120.12 r270 top
R14 "33R" R0805 -942.91,-335.83 r270 top
R15 "10KR" R0402 -963.53,475.14 r0 top
R16 "10KR" R0402 -1014.17,44.49 r0 top
R17 "10KR" R0402 -919.29,-420.71 r0 top
R18 "0R" R0402 742.43,-195.23 r330 top
R19 "0R" R0402 828.94,-547.24 r330 bottom
R20 "280KR" R0402 814.57,-459.25 r240 top
R21 "100KR" R0402 793.47,-506.45 r240 bottom
R22 "39KR" R0402 622.44,-550.98 r240 bottom
R23 "560KR" R0402 730.26,-515.52 r240 top
R24 "20KR" R0402 800.98,-408.86 r240 top
R25 "6.8KR" R0402 651.48,-567.6 r60 bottom
R26 "10KR" R0402 1043.71,611.69 r120 top
R27 "0R" R0402 833.46,686.81 r0 top
R28 "22R" R0402 1035.68,498.5 r300 top
R29 "22R" R0402 1008.41,482.75 r300 top
R30 "0R" R0402 841.56,601.48 r300 top
R31 "10R" R0402 -423.81,841.13 r0 top
R32 "4.7KR" R0402 -296.17,947.92 r0 top
R33 "10R" R0402 -299.41,1145.27 r0 top
R34 "10R" R0402 -423.81,806.68 r0 top
R35 "4.7KR" R0402 -296.17,983.33 r0 top
R36 "10R" R0402 -299.41,1109.84 r0 top
R37 "20KR" R0402 269.29,841.14 r0 top
R38 "10KR" R0402 269.49,802.36 r0 top
R39 "10KR" R0402 -227.17,820.06 r90 top
R40 "20KR" R0402 -296.17,1019.35 r0 top
R41 "10KR" R0402 -134.25,1109.25 r0 top
R42 "4.7KR" R0402 -315.35,802.94 r0 top
R43 "20KR" R0402 -262.01,1055.37 r180 top
R44 "4.7KR" R0402 -202.77,1109.84 r0 top
R45 "4.7KR" R0402 -315.35,845.06 r0 top
R46 "10R" R0402 -398.22,982.48 r0 top
R47 "4.7KR" R0402 -202.77,1145.27 r0 top
R48 "150KR" R0402 1127.17,-546.65 r60 top
R49 "1KR" R0402 1049.21,-562.01 r150 top
R50 "6.8KR" R0402 1090.26,-607.75 r60 top
R51 "1KR" R0402 338.19,857.48 r90 top
R52 "1KR" R0402 308.66,592.13 r180 top
R53 "10KR" R0402 269.29,910.83 r0 top
R54 "20KR" R0402 -315.35,877.76 r0 top
R55 "50mR" R2512-4 -809.25,116.73 r180 top
R56 "120R" R0603 1143.5,368.9 r30 top
R57 "20KR" R0402 -202.96,1214.26 r0 top
R58 "20KR" R0402 -315.35,913.18 r0 top
R59 "10R" R0402 -398.22,947.72 r0 top
R60 "20KR" R0402 -202.77,1180.21 r0 top
R66 "10KR" R0402 939.57,223.43 r30 top
R67 "120R" R0603 866.94,248.13 r30 top
R70 "10KR" R0402 858.27,176.77 r30 top
R71 "22R" R0402 701.57,619.69 r0 top
R72 "10KR" R0402 51.97,993.7 r180 bottom
R73 "22R" R0402 605.71,576.77 r0 top
R74 "22R" R0402 549.41,530.71 r0 top
R75 "10KR" R0402 359.06,547.44 r180 top
R76 "10KR" R0402 -506.89,893.11 r0 bottom
R77 "1KR" R0402 412.01,564.76 r90 top
R78 "1KR" R0402 -124.21,1070.67 r0 bottom
R79 "SDNT1608X103F3435FTF" R0603 -762.2,551.58 r180 bottom
U1 "KH-A1252VS-3P-CAP" CONN-SMD_3P-P1.25_KINGHELM_KH-A1252VS-3P-CAP 1104.53,-151.31 r0 top
U2 "STSPIN32G4" VFQFPN-64_L9.0-W9.0-P0.50-TL-EP4.0 13.78,889.56 r270 top locked
U4 "LP5907MFX-3.3" SOT23-5-2 936.02,-486.34 r330 top
U6 "TMI3252T" TSOT23-6 719.88,-619.09 r60 bottom
U7 "KH-A1252VS-3P-CAP" CONN-SMD_3P-P1.25_KINGHELM_KH-A1252VS-3P-CAP 570.08,830.12 r180 top
U8 "KH-A1252VS-3P-CAP" CONN-SMD_3P-P1.25_KINGHELM_KH-A1252VS-3P-CAP 1104.53,89.04 r0 top
U9 "CA-IF1044VD-Q1" DFN-8_3x3_EP_cheap 963.86,586.61 r210 top locked
U10 "SCT2A10STER" SOP8/1.27-cheap 655.75,-361.12 r60 top
U11 "D3485" SOIC-8_L4.9-W3.9-P1.27-LS6.0-BL 763.58,430.51 r210 top
U12 "KH-A1252VS-3P-CAP" CONN-SMD_3P-P1.25_KINGHELM_KH-A1252VS-3P-CAP 367.64,1062.8 r180 top
U13 "DU-01P" SW-SMD_2P-L5.4-W2.5-LS5.6 1121.26,262.4 r0 top
X1 "YF4020M" XTAL-S-23 28.94,1183.27 r270 top

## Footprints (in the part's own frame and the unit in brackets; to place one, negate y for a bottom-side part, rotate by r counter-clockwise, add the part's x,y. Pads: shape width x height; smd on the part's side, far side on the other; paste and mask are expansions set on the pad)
C0402 [mm] "片式电容,H=0.5+-0.2"
  rect 0.45x0.5 smd mask+0.076: 1(-0.425,0) 2(0.425,0)
  silkscreen extent -0.9,-0.45 0.9,0.45, body extent -0.5,-0.25 0.5,0.25, height 0.5
C0603 [mm] "片式电容;H=0.5~0.8+-0.2"
  rect 0.8x0.8 smd mask+0.076: 1(-0.706,0) 2(0.706,0)
  silkscreen extent -1.39,-0.62 1.39,0.62, body extent -0.8,-0.4 0.8,0.4, height 0.8
C1210 [mm]
  rect 1.635x2.7 smd paste-100 mask+0.051: 1(-1.517,0) 2(1.517,0)
  silkscreen extent -2.56,-1.58 2.56,1.58, body extent -2.2,-1.35 2.2,1.35, height 2.5
CONN-SMD_3P-P1.25_KINGHELM_KH-A1252VS-3P-CAP [mm]
  rect 0.6x1.7 smd paste+0 mask+0.05: 1(-1.25,1.7) 2(0,1.7) 3(1.25,1.7)
  rect 1x2.7 smd paste+0 mask+0.05: 4(3.1,-1.7) 5(-3.1,-1.7)
  silkscreen extent -3.65,-3.17 3.65,2.67, body extent -3.5,-3.15 3.5,1.9, height 4
CONN-SMD_SM06B-SURS-TF-LF-SN [mm]
  rect 0.5x1 smd: 1(-2,0.975) 2(-1.2,0.975) 3(-0.4,0.975) 4(0.4,0.975) 5(1.2,0.975) 6(2,0.975)
  rect 1.2x1.7 smd: 7(3.3,-0.975) 8(-3.3,-0.975)
  silkscreen extent -3.5,-1.42 3.5,1.18, body extent -3.5,-1.45 3.5,1.25, height 1.75
CONN-TH_XT30UPB-M [mm]
  round 2.5 hole 1.8: 1(-2.5,0) 2(2.5,0)
  silkscreen extent -5.14,-2.6 5.1,2.6, body extent -5.1,-2.8 5.1,2.8, height 10.7
D25_Power [mm]
  round 3 hole 2: 1(0,0)
DFN3.3X3.3-8L [mm]
  rect 1.98x2.8 smd: D(0,0)
  rect 0.6x0.4 smd: D(0.94,-0.975) D(0.94,0.975) D(0.94,-0.325) D(0.94,0.325) G(-2.01,-0.975) S(-2.01,0.975) S(-2.01,-0.325) S(-2.01,0.325)
  silkscreen extent -2.05,-1.65 1.1,1.65, body extent -2,-1.55 1.1,1.55, height 0.7
DFN65P100X45-2N [mm] "DFN, 2-Leads, Body 0.60x1.00mm, Pitch 0.65mm, IPC Medium Density"
  rect 0.35x0.6 smd: 1(-0.325,0) 2(0.325,0)
  silkscreen extent -0.57,0.68 -0.48,0.77
DFN-8_3x3_EP_cheap [mm]
  rect 0.35x0.625 smd paste+0 mask+0.05: 1(-0.975,-1.412) 2(-0.325,-1.412) 3(0.325,-1.412) 4(0.975,-1.412) 5(0.975,1.412) 6(0.325,1.412) 7(-0.325,1.412) 8(-0.975,1.412)
  rect 2.45x1.65 smd paste+0 mask+0.05: 9(0,0)
  silkscreen extent -1.58,-2.01 1.58,1.58, body extent -1.51,-1.5 1.5,1.51, height 0.75
DIODE-S-12 [mm] "Formosa MS ;BAV19WS THRU BAV21WS/PMEG2010BEA(高度为1.1mm)"
  rect 1x0.55 smd: A(1.35,0) K(-1.35,0)
  silkscreen extent -0.9,-0.68 0.9,0.68, body extent -1.35,-0.63 1.35,0.63, height 1
DIODE-SMB-3 [mm] "BrightKing,SMBJ6.0CA,0913_2018"
  rect 2.15x2.6 smd mask+0.051: A(2.225,0) K(-2.225,0)
  silkscreen extent -2.28,-1.97 2.29,1.97, body extent -2.7,-1.97 2.7,1.97, height 2.4
ICT2 [mm]
  oval 2x3 smd: 1(0,0)
L0603 [mil] "片式磁珠、电感、ESD"
  rect 32x31.5 smd mask+3: 1(-27.81,0) 2(27.81,0)
  silkscreen extent -50,-22 50,22, body extent -31,-16 31,16, height 31
L(2*1.6*1)-S [mm] "功率电感.004.004.0001830.4/8/2020;优化焊盘,0924_2021;优化焊盘,0524_2022"
  rect 0.9x1.7 smd paste-5: 1(-0.75,0) 2(0.75,0)
  Top Layer 1 pour cut-out: 0.275,-0.85 -0.275,-0.85 -0.275,0.85 0.275,0.85
  silkscreen extent -1.72,-1.1 1.45,1.09, body extent -1,-0.8 1,0.8, height 1
L(5*2.0)-S [mm] "SWPA5020S(Sunlord) :功率电感"
  rect 1.9x4.2 smd: 1(-2.1,0) 2(2.1,0)
  Top Layer 1 pour cut-out: -1.161,2.1 1.177,2.1 1.207,2.1 1.206,2.071 1.206,-2.112 -1.16,-2.112 -1.161,-2.111
  silkscreen extent -2.8,-2.6 3.56,2.6, body extent -2.5,-2.6 2.5,2.6, height 2
LED-S0603 [mm] "19-213-T1D-CNPHY-3T;14.06.18(19.01.15 优化焊盘，解决偏移问题。）"
  rect 0.75x0.8 smd: A(-0.725,0) K(0.725,0)
  silkscreen extent -1.32,-0.62 1.58,0.62, body extent -0.8,-0.4 0.8,0.4, height 0.8
MARK [mm] "SMD 使用"
  round 1.3 smd paste+0 mask+0.65: 0(0,0)
  Top Layer 1 circle w0.254: c0,0 r1.444
  Top Layer 1 pour cut-out: -1.3,0 -1.3,-0.128 -1.25,-0.379 -1.152,-0.616 -1.01,-0.829 -0.829,-1.01 -0.616,-1.152 -0.379,-1.25 -0.128,-1.3 0,-1.3 0.128,-1.3 0.379,-1.25 0.616,-1.152 0.829,-1.01 1.01,-0.829 1.152,-0.616 1.25,-0.379 1.3,-0.128 1.3,0 1.3,0.128 1.25,0.379 1.152,0.616 1.01,0.829 0.829,1.01 0.616,1.152 0.379,1.25 0.128,1.3 0,1.3 -0.128,1.3 -0.379,1.25 -0.616,1.152 -0.829,1.01 -1.01,0.829 -1.152,0.616 -1.25,0.379 -1.3,0.128 -1.3,0
R0402 [mm] "片式电阻;H=0.3~0.5+-0.2"
  rect 0.45x0.5 smd mask+0.076: 1(-0.425,0) 2(0.425,0)
  silkscreen extent -0.8,-0.4 0.8,0.4, body extent -0.5,-0.25 0.5,0.25, height 0.5
R0603 [mm] "贴片电阻,H=0.45~0.8+-0.1"
  rect 0.7x0.8 smd mask+0.076: 1(-0.756,0) 2(0.756,0)
  silkscreen extent -1.25,-0.54 1.25,0.54, body extent -0.8,-0.4 0.8,0.4, height 0.8
R0805 [mm] "贴片电阻;H=0.5~0.55+-0.15"
  rect 0.9x1.2 smd mask+0.076: 1(-0.866,0) 2(0.866,0)
  silkscreen extent -1.47,-0.75 1.47,0.75, body extent -1,-0.63 1,0.63, height 0.5
R2512-4 [mm] "H=H=0.55~1.1+-0.3,Walter,1201_2020"
  rect 1.7x3.7 smd: 1(-3.1,0) 2(3.1,0)
  silkscreen extent -2.18,-2 2.1,2, body extent -3.2,-1.6 3.2,1.6, height 1.4
SMA_L4.4-W2.6-LS5.0-RD [mm]
  rect 1.8x1.7 smd: 1(-2.193,0) 2(2.193,0)
  silkscreen extent -3.11,-1.48 2.73,1.48
SOIC-8_L4.9-W3.9-P1.27-LS6.0-BL [mm]
  oval 0.588x2.045 smd: 1(-1.905,-2.772) 2(-0.635,-2.772) 3(0.635,-2.772) 4(1.905,-2.772) 5(1.905,2.772) 6(0.635,2.772) 7(-0.635,2.772) 8(-1.905,2.772)
  silkscreen extent -2.8,-2.92 2.53,1.52, body extent -2.55,-2 2.56,2, height 1.8
SOP8/1.27-cheap [mm] "LOW POWER SEMI;LP28009(18.12.20 增大焊盘内延）"
  rect 1.4x0.8 smd: 1(-2.88,1.905)
  oval 1.4x0.8 smd: 2(-2.88,0.635) 3(-2.88,-0.635) 4(-2.88,-1.905) 5(2.88,-1.905) 6(2.88,-0.635) 7(2.88,0.635) 8(2.88,1.905)
  rect 2.55x3.2 smd paste-3 mask-3: 9(0,0)
  silkscreen extent -2.63,-2.5 4.16,3.03, body extent -3.1,-2.5 3.1,2.5, height 1.76
SOT23-5-2 [mm] "National Semiconductor ,LMV931(,FP6378AS5CTR  高度1.45mm）"
  oval 0.5x1.1 smd: 1(-0.95,-1.445) 2(0,-1.445) 3(0.95,-1.445) 4(0.95,1.445) 5(-0.95,1.445)
  silkscreen extent -2.13,-1.48 1.5,0.84, body extent -1.49,-0.83 1.5,0.84, height 1.3
SW-SMD_2P-L5.4-W2.5-LS5.6 [mm]
  rect 1.6x1 smd paste+0 mask+0.05: 1(-2.54,0) 2(2.54,0)
  silkscreen extent -2.67,-1.27 2.67,1.27, body extent -2.7,-1.25 2.7,1.25, height 2.3
TSOT23-6 [mm] "MP65151DJ[MPS]/MP1470"
  rect 1.1x0.5 smd: 1(-1.35,0.95)
  oval 1.1x0.5 smd: 2(-1.35,0) 3(-1.35,-0.95) 4(1.35,-0.95) 5(1.35,0) 6(1.35,0.95)
  silkscreen extent -1.47,-1.5 0.85,2.45, body extent -0.85,-1.5 0.85,1.5, height 1
VFQFPN-64_L9.0-W9.0-P0.50-TL-EP4.0 [mm]
  rect 0.79x0.28 smd paste-100 mask+0.05: 1(-4.495,3.75) 2(-4.495,3.25) 3(-4.495,2.75) 4(-4.495,2.25) 5(-4.495,1.75) 6(-4.495,1.25) 7(-4.495,0.75) 8(-4.495,0.25) 9(-4.495,-0.25) 10(-4.495,-0.75) 11(-4.495,-1.25) 12(-4.495,-1.75) 13(-4.495,-2.25) 14(-4.495,-2.75) 15(-4.495,-3.25) 16(-4.495,-3.75) 33(4.495,-3.75) 34(4.495,-3.25) 35(4.495,-2.75) 36(4.495,-2.25) 37(4.495,-1.75) 38(4.495,-1.25) 39(4.495,-0.75) 40(4.495,-0.25) 41(4.495,0.25) 42(4.495,0.75) 43(4.495,1.25) 44(4.495,1.75) 45(4.495,2.25) 46(4.495,2.75) 47(4.495,3.25) 48(4.495,3.75)
  rect 0.28x0.79 smd paste-100 mask+0.05: 17(-3.75,-4.495) 18(-3.25,-4.495) 19(-2.75,-4.495) 20(-2.25,-4.495) 21(-1.75,-4.495) 22(-1.25,-4.495) 23(-0.75,-4.495) 24(-0.25,-4.495) 25(0.25,-4.495) 26(0.75,-4.495) 27(1.25,-4.495) 28(1.75,-4.495) 29(2.25,-4.495) 30(2.75,-4.495) 31(3.25,-4.495) 32(3.75,-4.495) 49(3.75,4.495) 50(3.25,4.495) 51(2.75,4.495) 52(2.25,4.495) 53(1.75,4.495) 54(1.25,4.495) 55(0.75,4.495) 56(0.25,4.495) 57(-0.25,4.495) 58(-0.75,4.495) 59(-1.25,4.495) 60(-1.75,4.495) 61(-2.25,4.495) 62(-2.75,4.495) 63(-3.25,4.495) 64(-3.75,4.495)
  rect 4x4 smd paste-100 mask+0.05: 65(0,0)
  silkscreen extent -5.2,-4.58 4.58,4.58, body extent -4.5,-4.5 4.5,4.5, height 1
XTAL-S-23 [mm] "TXC.7XA2500020.2019/10/23"
  rect 1.4x1.1 smd: 1(-1.1,-0.85) 2(1.1,-0.85) 3(1.1,0.85) 4(-1.1,0.85)
  silkscreen extent -2.37,-1.93 1.65,1.3, body extent -1.65,-1.3 1.65,1.3, height 1

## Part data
C1 C2 C7 C9 C12 C14 C17 C19 C20 C28 C39 C40 C43 C45 C46 C48 C49 C50 C51 C52 C85 C86 C87: "50V,10%,X7R"
C3 C25: "100V,10%,X7R,0603B104K101NT"
C4 C34 C42 C53 C54 C55 C56 C57 C58 C59 C60 C61 C62 C63 C67 C68 C70 C71 C72 C73 C74 C78 C79: library part 10uF(100V), "100V,10uF, 10%,X7R,1210,FS32X106K101EGG"
C5 C6 C8 C10 C11 C13 C15 C16 C32 C33 C35 C36 C38 C44 C47: "25V,10uF, 20%,X5R,0603"
C18 C29: "50V,100pF, 5%,NPO,0402"
C21 C22 C23 C24 C26 C27: "50V,220pF, 5%,NPO,0402"
C30 C31: "50V,10pF, 5%,NPO,0402,SMD"
CN1 CN2: Colour=黄色, contact resistance=0.65mΩ, JLCPCB Part Class="Extended Part", LCSC Part Name="AMASS(艾迈斯)板载立式 航模锂电池控制器连接器插头 公头XT30UPB-M", Manufacturer=AMASS(艾迈斯), MaximumCurrent=-, RatedCurrent=15A, RatedVoltage="DC 500V"
CN4: Colour=白色, Current Rating (Max)=500mA, Flame Retardant Rating=UL94V-0, JLCPCB Part Class="Extended Part", LCSC Part Name="1x6P 间距:0.8mm 卧贴 系列:SUR", Manufacturer=JST, Operating Temperature Range=-25℃~+85℃, Rated Voltage (Max)=30V
D1: JLCPCB Part Class="Extended Part", Manufacturer=SHIKUES(时科), Power Dissipation=1W, Reverse Leakage Current (Ir)=1uA@56V, Tolerance=-, Zener Voltage (Nom)=75V, Zener Voltage (Range)=71.2V~78.8V
L1: "功率电感,Power Inductor,15uH, 20%,1.25A", DC Resistance (DCR)=214.5mΩ, JLCPCB Part Class="Extended Part", LCSC Part Name="15uH ±20%", Manufacturer=FH(风华), Manufacturer Part=PRS5020-150MT, Rated Current=1.25A, Tolerance=±20%
L2: "功率电感,4.7uH,1.2A,2.0 1.6 1.05mm,SMD,CKCSA201610-4.7uH/M", DC Resistance (DCR)=214.5mΩ, JLCPCB Part Class="Extended Part", LCSC Part Name="15uH ±20%", Manufacturer=FH(风华), Manufacturer Part=PRS5020-150MT, Rated Current=1.25A, Tolerance=±20%
L3: "磁珠,BEAD,120ohm,0603,2000mA,SMD", DC Resistance (DCR)=214.5mΩ, JLCPCB Part Class="Extended Part", LCSC Part Name="15uH ±20%", Manufacturer=FH(风华), Manufacturer Part=PRS5020-150MT, Rated Current=1.25A, Tolerance=±20%
Q1 Q2 Q3 Q4 Q5 Q6: "新洁能 MOS"
Q7 Q8 Q10 Q14: "小信号类TVS管,D,5pF,12V,DFN1006,SMD"
Q9: "稳压管3.3V,500mW,SOD-123,"
Q11 Q12: "贴片LED 0603"
Q13: "TVS管,DIO ESD,93.6V,SMB"
R1 R20: "1/16W,280kohm, 1%,0402"
R2 R24 R37 R40 R43 R54 R57 R58 R60: "1/16W,20kohm, 1%,0402"
R3 R5 R55: "贴片合金电阻,2W,50mohm, 1%,2512"
R4 R9 R10 R11 R15 R16 R17 R26 R38 R39 R41 R53 R66 R70 R72 R75 R76: "1/16W,10Kohm, 1%,0402"
R6 R7 R8 R12 R13 R14: "1/8W,33ohm, 5%,0805"
R18 R19 R27 R30: "1/16W,0ohm, 5%"
R21: "1/16W,100kohm, 1%,0402"
R22: "1/16W,39kohm, 1%,0402"
R23: "1/16W,560kohm, 1%,0402"
R25 R50: "1/16W,6.8kohm, 1%,0402"
R28 R29 R71 R73 R74: "1/16W,22ohm, 1%,0402"
R31 R33 R34 R36 R46 R59: "1/16W,10ohm, 1%,0402"
R32 R35 R42 R44 R45 R47: "4.7kohm, 1%,0402"
R48: "1/16W,150kohm, 1%,0402"
R49 R51 R52 R77 R78: "1/16W,1kohm, 1%,0402"
R56 R67: "1/10W,120ohm, 1%,0603"
R79: "ntc,B 3435k,10kohm, 1%,0603"
U1 U7 U8 U12: JLCPCB Part Class="Extended Part", Manufacturer=kinghelm(金航标)
U2: library part STSPIN32G4_C7434864, "STM32G4 MCU", JLCPCB Part Class="Extended Part", Manufacturer=ST(意法半导体)
U6: "DC-DC,4.5～18V,2A,600kHz,SOT23-6"
U9: "Chipanalog(川土微) CAN"
U10: "DC-DC,4.5～85V,0.6A,300-800kHz,0.8A,ESOP-8"
U11: JLCPCB Part Class="Extended Part", Manufacturer=Silicore(芯谷), Operating Temperature=-, Supply Voltage=5V
U13: Color=黑色, Current Rating=25mA, JLCPCB Part Class="Extended Part", LCSC Part Name="1.27mm间距1位 贴片黑色J脚 拨码开关", Manufacturer=HANBO(汉博), Operating Life=3千次, Operating Temperature=-40℃~+85℃, Voltage Rating=24V
X1: "有源普通晶振,20MHz, 40ppm,3.3V,SMD3225"

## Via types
v1: diameter 23.62, hole 11.81, Top Layer 1 to Bottom Layer 1, 146 vias
v2: diameter 39.37, hole 19.68, Top Layer 1 to Bottom Layer 1, 21 vias
v3: diameter 86.61, hole 86.61, Top Layer 1 to Bottom Layer 1, 6 vias
v4: diameter 19.68, hole 11.81, Top Layer 1 to Bottom Layer 1, 4 vias
v5: diameter 19.68, hole 11.81, Top Layer 1 to Bottom Layer 1, tented top, 2 vias

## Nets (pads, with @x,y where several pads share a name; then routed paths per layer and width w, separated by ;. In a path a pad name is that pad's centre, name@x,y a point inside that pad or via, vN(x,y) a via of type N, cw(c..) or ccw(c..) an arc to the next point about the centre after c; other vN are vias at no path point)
3V3: C15.2 C16.2 C17.2 C19.2 C44.2 C45.2 C47.2 C48.2 C49.2 C50.2 C51.2 C52.2 L3.1 R37.2 R51.2 R52.2 R53.2 R72.2 R75.2 U2.1 U2.2 U2.64 U4.5 U9.5 X1.1 X1.4 | length 1408.3
  Top Layer 1 w10: C48.2@-70.28,1240.16 -37.32,1240.16 cw(c-37.32,1193.78) X1.1@-4.53,1226.57 X1.4@62.4,1226.57 79.06,1226.57 C44.2@138.02,1226.57 ; C50.2@130.51,1125.79 C50.2@131.07,1125.77 ; U2.2@141.73,1066.52 141.73,1114.57 ccw(c130.51,1114.57) C50.2@131.07,1125.77 ; U2.1@161.42,1066.52 161.42,1115.75 cw(c170.67,1115.75) C19.2@170.67,1125 ; U2.64@190.75,1037.2 v2(245.91,1037.2) 211.65,1070.75 cw(c225.71,1084.98) 205.71,1084.89 205.71,1101.18 ccw(c181.89,1101.18) 181.89,1125 C19.2@170.67,1125 ; v1(264.96,592.13) R52.2@291.93,592.13 ccw(c336.61,592.13) 336.61,547.44 R75.2@342.32,547.44 ; R37.2@286.02,841.14 v1(286.02,874.61) ; R53.2@286.02,910.83 v1(286.02,874.61) ; R51.2@338.19,874.21 333.35,874.26 332.51,874.26 v1(286.02,874.61) ; v1@906.61,530.26 908.69,529.7 cw(c894.57,476.54) 942.23,503.99 947.12,495.53 ccw(c958.61,505.16) 947.7,494.88 951.41,490.94 ccw(c966.02,504.6) 955.17,487.8 964.93,481.43 C49.2@971.06,480.51 970.97,484.91 967.46,490.99 cw(c1021.01,503.52) 966.02,504.6 961.42,512.56 U9.5@958.43,519.26 ; C50.2@131.07,1125.77 135.35,1125.67 136.66,1125.67 164.46,1125.12 165.83,1125.12 C19.2@170.67,1125
  Bottom Layer 1 w10: L3.1@2.36,934.58 cw(c65.72,934.58) 20.92,979.38 R72.2@35.24,993.7 ; C47.2@164.82,968.07 cw(c208.29,968.07) 177.55,998.81 194.74,1016 cw(c245.91,964.83) v2(245.91,1037.2) ; C52.2@203.6,1066.8 216.31,1066.8 cw(c216.31,1037.2) v2(245.91,1037.2) ; C45.2@283.46,1016.93 ccw(c263.2,1016.93) 263.2,1037.2 v2(245.91,1037.2)
  Bottom Layer 1 w20: L3.1@2.36,934.58 C51.2@2.36,895.08 ccw(c47.03,939.75) 47.03,876.57 v1(116.93,876.57) v1(116.93,836.42)
  other v1: 907.65,529.98 199.33,1117.4 103.94,1226.77
  other v2: 965.43,-320.32
5V: C10.2 C11.2 C12.2 C13.2 C14.2 C18.2 C20.2 C85.2 CN4.1 L2.2 R22.2 R70.1 U4.1 U4.3 U9.3 U11.8 | length 2856.7
  Top Layer 1 w10: v2(787.2,165.77) 789.84,168.41 R70.1@843.78,168.41 ; v1(867.32,639.76) 887.5,654.06 C20.2@890.66,656.3 895.58,653.54 905.49,648 cw(c895.71,630.55) 910.36,644.16 ; 910.39,644.13 919.89,633.87 U9.3@924.97,628.37
  Top Layer 1 w20: CN4.1@734.84,105.51 744.37,105.51 783.5,144.64 783.5,162.06 v2(787.2,165.77) ; v2(794.88,-671.06) 794.88,-665.82 822.96,-637.74 C13.2@822.96,-631.53 ; C14.2@841.5,-575.24 U4.1@875.19,-516.9 ; C14.2@841.85,-575.45 ccw(c887.45,-621.05) 822.96,-621.05 C13.2@822.96,-631.53 ; U11.8@883.11,373.49 896.39,350.48 896.92,350.78 C85.2@919.96,312.89 v1@942.19,274.62 ; U4.3@939.97,-554.3 907.54,-610.48 cw(c856.71,-559.65) 856.71,-631.53 C13.2@822.96,-631.53
  POWER w10: v1(625.07,-620.8) 664.94,-660.67 ccw(c735.65,-589.96) 735.65,-689.96 756.5,-689.96 ccw(c756.5,-642.91) 789.76,-676.18 v2(794.88,-671.06) ; v1(867.32,639.76) 867.32,389.76 ccw(c967.32,389.76) 896.61,319.05 v1(941.46,274.2)
  POWER w20: v2(794.88,-671.06) 802.8,-663.15 ccw(c732.09,-592.44) 832.09,-592.44 832.09,118.44 ccw(c807.22,118.44) 824.8,136.02 800.61,160.22 ccw(c787.2,146.82) v2(787.2,165.77) 866.34,244.91 cw(c937.05,174.2) 937.05,274.2 v1(941.46,274.2)
  SIG w10: v2(610.83,-889.57) 595.23,-873.97 cw(c665.94,-803.26) 565.94,-803.26 565.94,-698.45 cw(c647.27,-698.45) 589.76,-640.94 599.19,-631.52 cw(c625.07,-657.39) v1(625.07,-620.8)
  Bottom Layer 1 w20: C11.2@557.25,-771.81 560.13,-766.83 580.54,-731.47 C10.2@583.42,-726.49 ; C18.2@588.29,-549.33 R22.2@614.07,-565.47 ccw(c723.86,-572.41) 613.98,-567.17 613.18,-584.03 ccw(c630.16,-584.84) 613.97,-590.04 619.14,-606.11 ccw(c723.86,-572.41) v1(625.07,-620.8)
  Bottom Layer 1 w30: v2(610.83,-889.57) 610.83,-887.03 628.19,-869.67 628.19,-819.26 L2.2@626.35,-817.42
12V: C5.2 C6.2 C7.2 C8.2 C9.2 C35.2 C43.2 L1.2 R20.2 R21.1 U2.63 U6.3 | length 2828.5
  Top Layer 1 w10: v1(150.56,1017.51) U2.63@190.75,1017.51 ; v1(763.61,-459.25) ccw(c780.34,-406.86) 766.02,-459.96 780.09,-463.75 cw(c765.76,-516.86) 793.26,-469.23 800.73,-473.54 R20.2@806.2,-473.74
  SIG w10: v1(150.56,1017.51) 212.39,955.68 ccw(c270.47,1013.34) 270.47,931.5 cw(c270.47,837.87) 336.78,903.97 422.9,817.85 ccw(c461.79,856.74) 454.37,802.25 cw(c446.9,747.75) 485.85,786.59 706.46,565.98 cw(c634.12,493.37) 736.61,493.23 736.61,-370.33 cw(c681.61,-370.33) 720.55,-409.18 708,-421.73 ccw(c746.93,-460.58) 691.93,-460.58 691.93,-515.54 691.93,-577.98 cw(c591.93,-577.98) 662.64,-648.69 v2(627.51,-683.82)
  Bottom Layer 1 w10: C6.2@113.19,1011.18 cw(c113.19,1010.18) 114.19,1010.18 C7.2@114.19,957.78 ; C6.2@114.19,1017.51 v1(150.56,1017.51) ; L1.2@614.41,-432.72 681.33,-472.17 689.87,-477.1 ccw(c717.37,-429.47) v1@763.59,-459.28 ; v1@763.62,-459.26 797.16,-487.96 798.21,-488.56 R21.1@801.84,-491.96
  Bottom Layer 1 w20: C35.2@505.19,-588.74 541.38,-612.43 549.39,-617.67 C9.2@573.41,-633.39 ; C9.2@573.42,-633.4 cw(c562.67,-650.26) 573.54,-633.47 582.33,-639.1 588.83,-643.26 cw(c529.54,-735.91) 619.05,-671.98 626.62,-682.58 v2(627.51,-683.82) ; v2@627.26,-676.31 v2@627.45,-681.99 ; U6.3@660.91,-646.42 655.01,-656.65 637.32,-672.15 ccw(c709.92,-754.78) v2@627.45,-681.99 ; v2@627.45,-681.99 v2(627.51,-683.82) ; v2@627.45,-681.99 v2(627.51,-683.82)
  Bottom Layer 1 w30: C35.2@505.19,-588.74 525.9,-553.62 526.85,-552.01 ccw(c384.75,-468.16) 527.71,-550.54 528.59,-549.02 C8.2@528.99,-548.38 ; C8.2@528.95,-548.22 C5.2@557.17,-502.36 C5.2@557.71,-501.81 ; C5.2@557.72,-501.78 cw(c687.92,-603.14) 560.45,-498.37 564.26,-493.74 cw(c691.79,-598.43) 564.39,-493.58 591.39,-460.73 ccw(c464.15,-355.68) 599.46,-450.11 599.52,-450 L1.2@614.41,-432.72
48V: C3.2 C4.2 C25.2 C34.2 C42.2 C53.2 C54.2 C55.2 C56.2 C57.2 C58.2 C59.2 C60.2 C61.2 C62.2 C63.2 C67.2 C68.2 C70.2 C71.2 C72.2 C73.2 C74.2 C78.2 C79.2 CN1.2 CN2.2 D1.1 Q1.D Q3.D Q5.D Q13.K R1.1 R48.2 U2.61 U2.62 U10.2 | length 5376.8
  Top Layer 1 w10: U2.61@190.75,978.14 v1(251.96,978.14) ccw(c232.27,978.14) 232.27,997.83 U2.62@190.75,997.83 ; C72.2@556.64,-619.87 560.05,-668.02 ccw(c575.05,-668.02) 560.42,-671.3 ccw(c614.03,-659.02) 561.91,-676.58 ccw(c656.64,-644.55) 564.76,-684.03 ccw(c656.64,-644.55) 585.87,-715.21 588.29,-717.62 ccw(c658.94,-646.85) 658.94,-746.85 683.79,-746.85 ccw(c683.68,-691.85) 720.71,-732.52 cw(c759.19,-774.55) 759.19,-717.56 792.61,-717.56 ccw(c792.61,-658.95) 834.03,-700.42 852.67,-681.77 cw(c891.48,-720.75) 889.47,-665.79 ccw(c887.45,-606.84) 929.16,-648.55 958.18,-619.46 970.5,-607.14 ccw(c957.25,-593.9) 975.98,-593.9 cw(c1041.63,-593.9) 995.21,-547.48 1056.33,-486.36 cw(c1118.7,-548.73) C4.2@1118.7,-460.53 ; C72.2@556.64,-580.31 R1.1@620.71,-580.31 ; C4.2@1070.55,-487.71 C4.2@1118.7,-460.53 ; R48.2@1135.53,-532.16 cw(c1176.16,-491.53) 1118.7,-491.53 C4.2@1118.7,-460.53
  Top Layer 1 w30: Q13.K@507.18,-922.96 507.18,-903.86 515.4,-895.64 ccw(c399.76,-777.94) 564.76,-778.12 C72.2@564.76,-625.75 ; C72.2@556.64,-619.87 552.91,-587.31 cw(c716.86,-568.75) 552.27,-580.31 C3.2@552.27,-523.96 552.59,-523.21 cw(c717.2,-534.46) U10.2@577.4,-446.82
  Top Layer 1 w50: CN1.2@276.87,-935.76 278.4,-935.28 cw(c359.79,-1197.96) 359.56,-922.96 Q13.K@479.22,-922.96 ; v2(428.04,-984.97) Q13.K@479.22,-922.96 ; Q13.K@507.18,-922.96 Q13.K@479.22,-922.96
  SIG w10: v1(251.96,978.14) 383.22,978.14 cw(c383.22,923.14) 422.07,962.07 1057.36,326.78 cw(c1018.43,287.94) 1073.43,287.94 1073.43,-364.05 cw(c988.07,-364.05) 1048.43,-424.41 1032.44,-440.4 ccw(c1103.15,-511.11) 1003.15,-511.11 1003.15,-545.78 cw(c903.15,-545.78) 973.86,-616.49 634.67,-955.68 cw(c563.96,-884.97) 563.96,-984.97 v2(428.04,-984.97)
  Bottom Layer 1 w10: C25.2@162.99,856.75 168.66,856.75 ccw(c168.66,941.04) D1.1@252.95,941.04
  Bottom Layer 1 w50: C79.2@-539.38,-742.43 C61.2@-539.38,-670.67 ; C74.2@-403.35,-821.74 C62.2@-403.35,-734.26 ; C59.2@-268.9,-880.5 C78.2@-268.9,-794.59 ; C60.2@-133.46,-910.47 v2(-133.46,-825.39) ; CN1.2@276.87,-935.76 ccw(c341.11,-871.52) 341.11,-962.37 412.31,-962.37 ccw(c412.31,-862.37) 483.02,-933.08 C42.2@515.98,-900.13
  other v1: 4.92,-1238.58 148.43,-1226.97 299.8,-1202.95 4.92,-1164.76 148.43,-1153.15 299.8,-1129.13 -669.36,-1032.97 -669.36,-959.15 -1017.13,-695.08 -943.31,-695.08 -839.4,-695.08 -765.58,-695.08 -1149.8,-495.08 -1182.67,-401.93 -1108.85,-401.93 -1217.13,-284.21 -1143.31,-284.21 -1253.74,-169.88 -1179.92,-169.88 -1266.09,-58.27 -1243.7,52.76 -1169.88,52.76 -1233.25,154.21 -1159.44,154.21 -1219.88,247.44 -1146.06,247.44 -1215.77,357.68
  other v2: -268.9,-796.85 -403.74,-736.42 -540.16,-670.67
485_DIR: R73.1 U2.12 | length 920.3
  Top Layer 1 w10: v1(-64.28,1028.25) -58.93,1042.58 ccw(c-110.46,1061.82) -56.31,1052.18 -55.63,1055.97 U2.12@-55.12,1066.52 ; v1(556.89,575.79) cw(c564.23,521.28) 564.13,576.28 585.12,576.28 R73.1@588.98,576.77
  SIG w10: v1(-64.28,1028.25) -43.84,1048.7 cw(c-4.99,1009.76) -4.99,1064.76 41.52,1064.76 cw(c41.52,991.96) 68.82,1059.45 cw(c48.15,1008.48) 99.07,1029.28 105.55,1013.51 ccw(c156.46,1034.32) 117.49,995.5 260.47,852.53 ccw(c299.36,891.42) 299.36,836.42 299.91,836.42 cw(c299.81,781.42) 350.19,803.48 357.08,788.02 ccw(c407.31,810.43) 368.31,771.65 372.41,767.55 ccw(c411.2,806.54) 374.68,765.41 382.77,758.23 cw(c346.26,717.1) 385.22,755.92 543.48,597.66 cw(c504.59,558.77) 556.87,575.86 v1(556.89,575.79)
485_IN: R71.1 U2.9 | length 887.6
  Top Layer 1 w10: U2.9@3.94,1066.52 4.45,1066.01 4.45,1035.06 10.04,1029.47 v1(10.04,1025.79) ; v1(456.3,622.24) 458.86,619.69 R71.1@684.84,619.69
  SIG w10: v1(10.04,1025.79) ccw(c64.57,1032.93) 37.24,985.21 ccw(c70.49,1043.44) 70.49,976.38 75.59,976.38 cw(c75.59,919.35) 115.92,959.67 151.85,923.74 ccw(c190.69,962.68) 152.99,922.63 158.89,917.07 cw(c121.12,877.08) 160.02,915.96 445.23,630.75 ccw(c484.02,669.75) v1(456.3,622.24)
485_OUT: R74.1 U2.10 | length 813.5
  Top Layer 1 w10: U2.10@-15.75,1066.52 -15.24,1061.04 -15.24,1060.97 -15.35,1060.85 v1(-15.35,989.96) ; v1(500.98,530.71) R74.1@532.68,530.71
  SIG w10: v1(-15.35,989.96) -10.18,984.79 ccw(c56.69,1051.66) 55.15,957.1 cw(c54.17,902.11) 93,941.06 141.48,892.58 cw(c102.59,853.69) 152.24,877.34 161.83,857.21 ccw(c211.48,880.86) 172.49,842.08 465.57,548.99 ccw(c504.36,587.99) 485.61,536.28 v1(500.98,530.71)
485A: CN4.3 Q14.2 R67.1 R70.2 U11.6 | length 435.3
  Top Layer 1 w10: CN4.3@734.84,42.52 788.57,42.52 ccw(c788.57,57.3) 799.02,46.85 832.77,46.85 ccw(c832.77,101.29) 871.26,62.8 ccw(c836.09,97.96) 885.83,97.96 885.83,153.59 ccw(c841.21,153.59) R70.2@872.76,185.14 867,187.4 870.34,189.33 870.42,189.38 852.82,221.36 847.64,230.78 842.44,240.19 808.55,301.65 808.97,301.89 U11.6@796.51,323.49
485B: CN4.4 Q10.2 R66.1 R67.2 U11.7 | length 548
  Top Layer 1 w10: CN4.4@734.84,11.02 790.75,11.02 794.49,7.28 856.54,7.28 ccw(c856.54,77.99) 906.54,27.99 ccw(c835.83,98.7) 935.83,98.7 935.83,189.1 ccw(c899.12,189.1) R66.1@925.08,215.06 922.68,219.27 904.53,251.21 899.22,260.56 886.24,265.48 893.18,269.49 855.24,325.64 853.56,324.67 U11.7@839.81,348.49
A: A.1 C32.1 Q1.S Q2.D R9.2 U2.42 | length 1223.3
  Top Layer 1 w10: U2.42@43.31,712.59 43.82,712.08 43.82,693.72 62.55,675 104.01,675 v1(135.68,643.33)
  SIG w10: A.1@-794.29,332.09 ccw(c-799.36,386.85) -760.56,347.88 -500.61,607.83 cw(c-256.22,363.43) -256.22,709.06 -22.39,709.06 cw(c-22.39,654.06) 16.58,692.87 50.02,659.43 ccw(c88.9,698.33) 88.9,643.33 111.98,643.33 ccw(c111.98,698.33) 112.12,643.33 133.15,643.38 cw(c133.29,588.38) v1(135.68,643.33)
  other v1: -1028.54,268.5 -1028.54,309.25 -1028.54,349.8
A3V3: C28.2 C38.2 C39.2 C40.2 L3.2 R40.1 R54.1 R57.1 R76.2 U2.26 U2.27 | length 451.2
  Top Layer 1 w10: v1(-407.08,899.4) -407.01,899.4 -385.37,877.76 R54.1@-332.09,877.76 ; v1@-349.08,1017.51 cw(c-347.24,1017.51) v1(-347.24,1019.35) R40.1@-312.91,1019.35 ; v1(-282.68,1214.26) R57.1@-219.69,1214.26 ; U2.27@-163.19,840.35 ccw(c-163.19,897.24) -111.05,874.49 ; U2.26@-163.19,860.03 -138.8,860.03 ccw(c-138.8,893.88) -111.05,874.49 ; v2(-106.3,933.23) -106.3,897.24 cw(c-163.19,897.24) -111.05,874.49
  Bottom Layer 1 w10: R76.2@-490.16,893.11 -440.55,893.11 -422.26,893.11 ccw(c-422.26,914.57) v1(-407.08,899.4)
AMP1_N: C24.2 R39.1 R42.2 U2.25 | length 198.9
  Top Layer 1 w8: R42.2@-298.62,802.94 -298.33,803.23 -263.88,803.23 C24.2@-263.58,803.53 -263.48,803.43 -227.26,803.43 R39.1@-227.17,803.33 -215.17,803.33 ccw(c-215.17,820.06) -198.44,820.06 -198.44,865.54 cw(c-184.26,865.54) -184.26,879.72 U2.25@-163.19,879.72
AMP1_P: R45.2 R54.2 R58.2 U2.23 | length 206
  Top Layer 1 w10: R45.2@-298.62,845.06 R54.2@-298.62,877.76 R58.2@-298.62,913.18 -253.74,913.18 -247.83,919.09 U2.23@-163.19,919.09
AMP2_N: C22.2 R4.1 R32.2 U2.22 | length 121.8
  Top Layer 1 w10: R32.2@-279.44,947.92 -248.34,947.92 ccw(c-248.34,953.65) C22.2@-244.29,949.6 -210.37,949.6 ccw(c-210.37,952.56) R4.1@-208.28,950.47 -207.3,950.47 -195.6,938.77 U2.22@-163.19,938.77
AMP2_P: R35.2 R40.2 R43.2 U2.20 | length 301
  Top Layer 1 w10: R35.2@-279.44,983.33 R40.2@-279.44,1019.35 ; R43.2@-279.44,1055.37 R40.2@-279.44,1019.35 ; v1(-246.14,1019.35) R40.2@-279.44,1019.35 ; U2.20@-163.19,978.14 -144.3,978.14 ccw(c-144.3,996.65) -125.79,996.65 -125.79,1014.96 cw(c-122.44,1014.96) v1(-122.44,1018.31)
  Bottom Layer 1 w10: v1(-246.14,1019.35) -123.48,1019.35 v1(-122.44,1018.31)
AMP3_N: C27.2 R41.1 R44.2 U2.16 | length 124.6
  Top Layer 1 w10: R44.2@-186.04,1109.84 -185.74,1109.55 -151.28,1109.55 R41.1@-150.99,1109.25 ; C27.2@-150.99,1146.06 R41.1@-150.99,1109.25 ; U2.16@-133.86,1066.52 cw(c-133.86,1082.27) -149.61,1082.27 -149.61,1107.87 ccw(c-150.99,1107.87) R41.1@-150.99,1109.25
AMP3_P: R47.2 R57.2 R60.2 U2.14 | length 283.1
  Top Layer 1 w10: R57.2@-186.23,1214.26 R57.2@-186.03,1214.26 ; R47.2@-186.04,1145.27 R60.2@-186.03,1180.21 R57.2@-186.03,1214.26 ; U2.14@-94.49,1066.52 -94.49,1155.12 ccw(c-153.64,1155.12) -153.64,1214.26 R57.2@-186.03,1214.26
B: B.1 C33.1 Q3.S Q4.D R10.2 U2.39 | length 1410.6
  Top Layer 1 w10: U2.39@-15.75,712.59 -15.75,664.37 v1(5.29,643.33)
  SIG w10: B.1@-848.82,-102.36 -751.3,-4.85 ccw(c-790.24,34) -735.24,34 -735.24,147.28 cw(c-680.24,147.28) -734.44,156.62 -713.11,281.87 cw(c-658.91,272.56) -710.55,291.48 cw(c-329.08,152.04) -616.27,439.24 -477.97,577.54 cw(c-241.26,340.82) -241.26,675.59 -53.49,675.59 cw(c-53.49,620.59) -14.64,659.52 -9.79,654.67 ; -9.79,654.67 -9.69,654.56 -9.59,654.47 ccw(c29,693.66) -9.16,654.05 -7.65,652.6 ccw(c30.51,692.21) v1(5.29,643.33)
  other v1: -1021.49,-197.75 -792.91,-196.85 -1079.33,-169.88 -1079.33,-88.58
BOOTA: C32.2 U2.41 | length 104.7
  Top Layer 1 w10: U2.41@23.62,712.59 23.62,690.49 ccw(c51.12,690.49) 29.17,673.92 40.07,659.44 40.11,659.38 ccw(c62.04,675.97) 40.61,658.74 45.54,652.63 45.59,652.58 ccw(c66.93,669.92) 66.93,642.42 69.31,642.42 C32.2@80.06,639.59
BOOTB: C33.2 U2.38 | length 81.5
  Top Layer 1 w10: C33.2@-50.33,639.59 ccw(c-50.33,654.5) -35.43,654.5 U2.38@-35.43,712.59
BOOTC: C36.2 U2.35 | length 142.9
  Top Layer 1 w10: C36.2@-191,641.54 cw(c-151.43,641.54) -151.43,681.1 -123.84,681.1 -119.91,685.04 -103.69,685.04 -95,693.72 -95,712.08 U2.35@-94.49,712.59
BRK_OC: U2.44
